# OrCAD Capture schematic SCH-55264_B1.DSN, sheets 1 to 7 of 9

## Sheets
1 09 Jumper Tables: size C; title: IMX-DSI-SDSB; rev: B1; company: NXP Semiconductors; note: SCH-55264 PDF: SPF-55264; note: 6501 William Cannon Drive West; note: Austin, TX 78735-8598
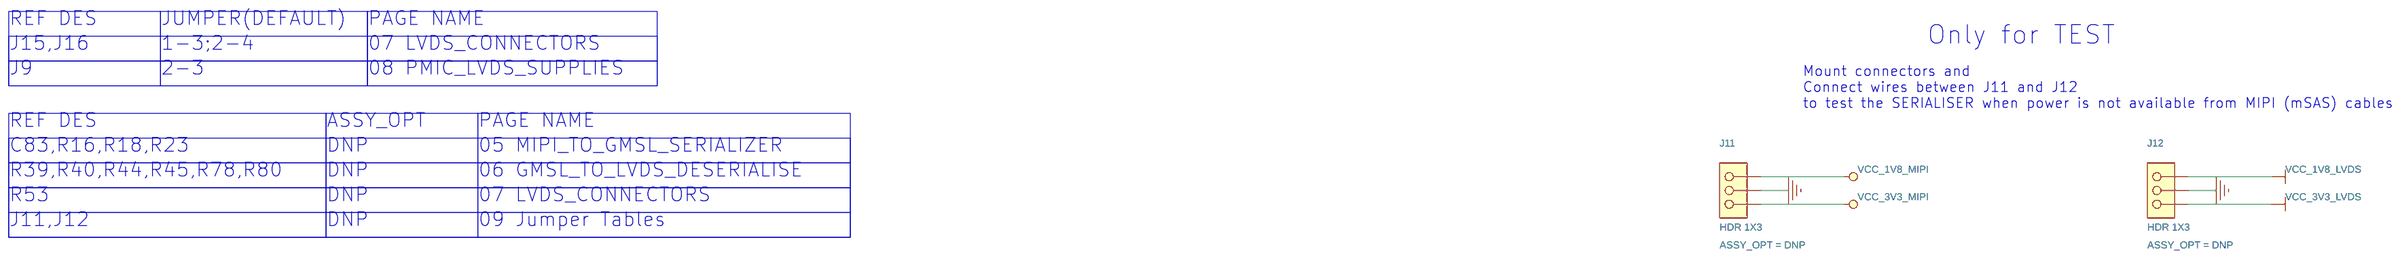
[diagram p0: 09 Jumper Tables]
2 01 TITLE
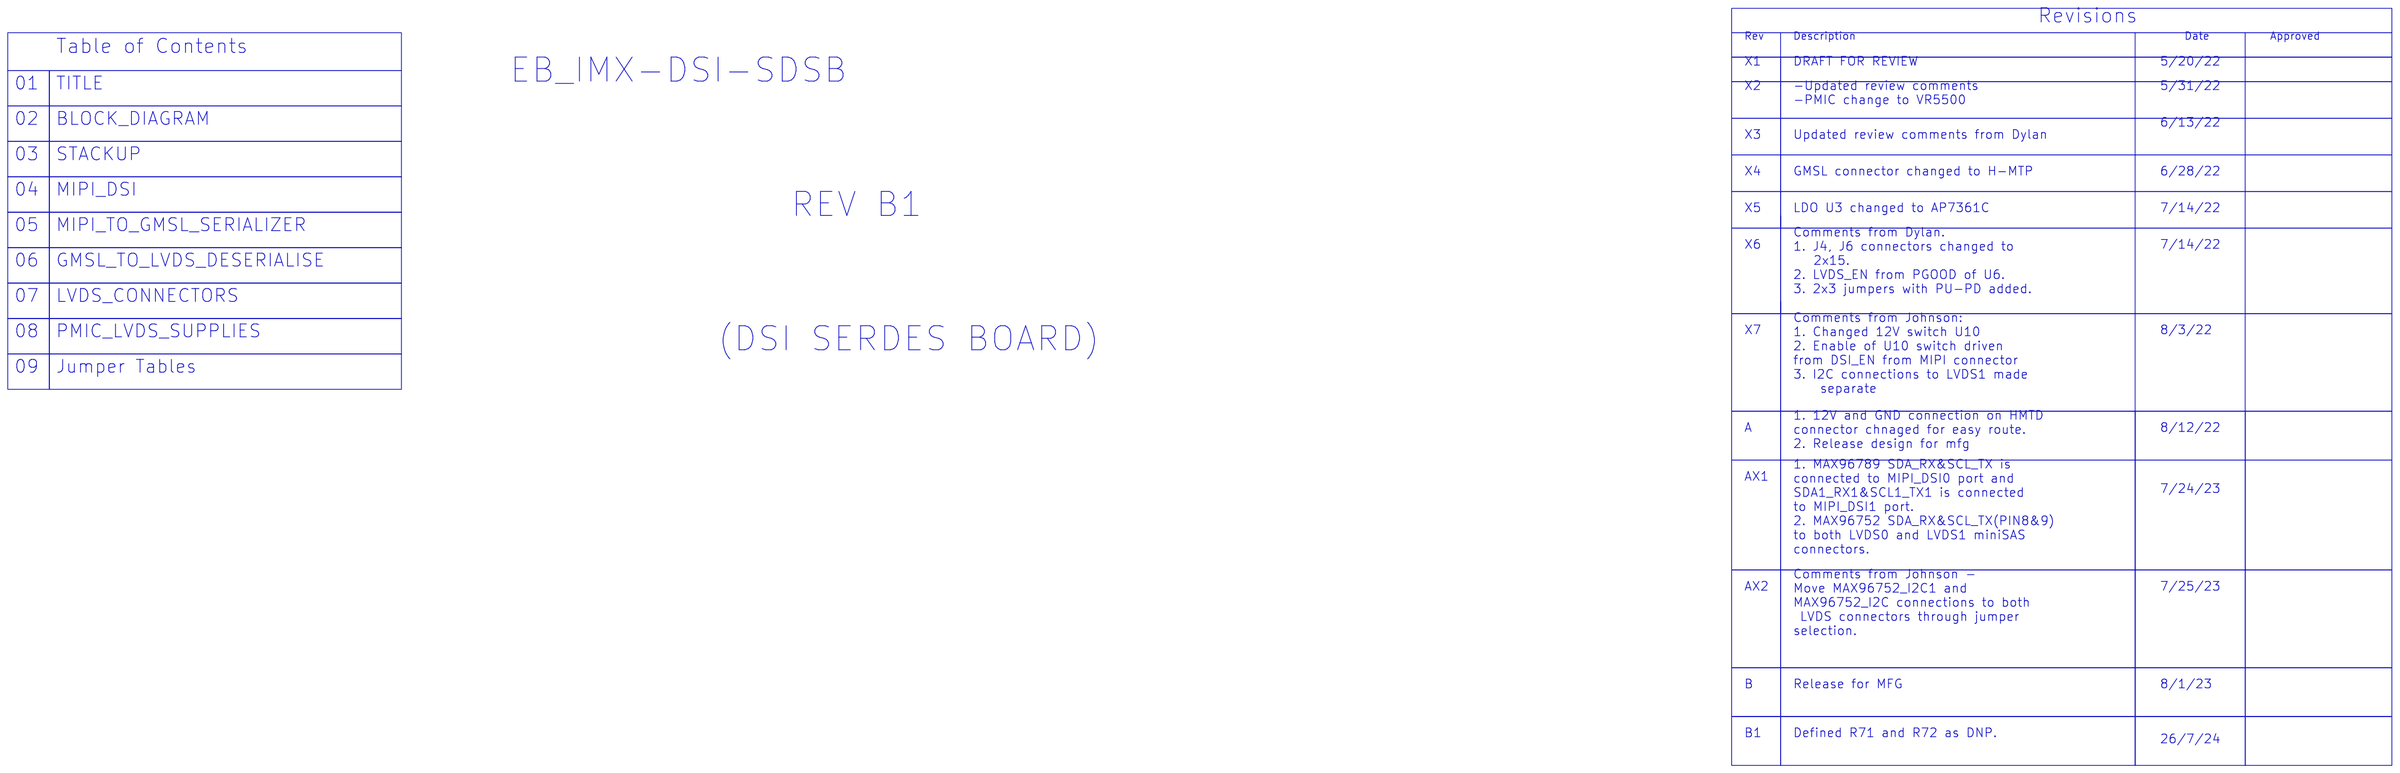
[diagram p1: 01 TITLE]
3 02 BLOCK_DIAGRAM
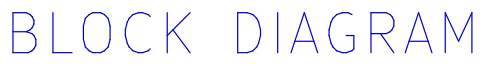
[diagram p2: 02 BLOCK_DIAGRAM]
4 03 STACKUP
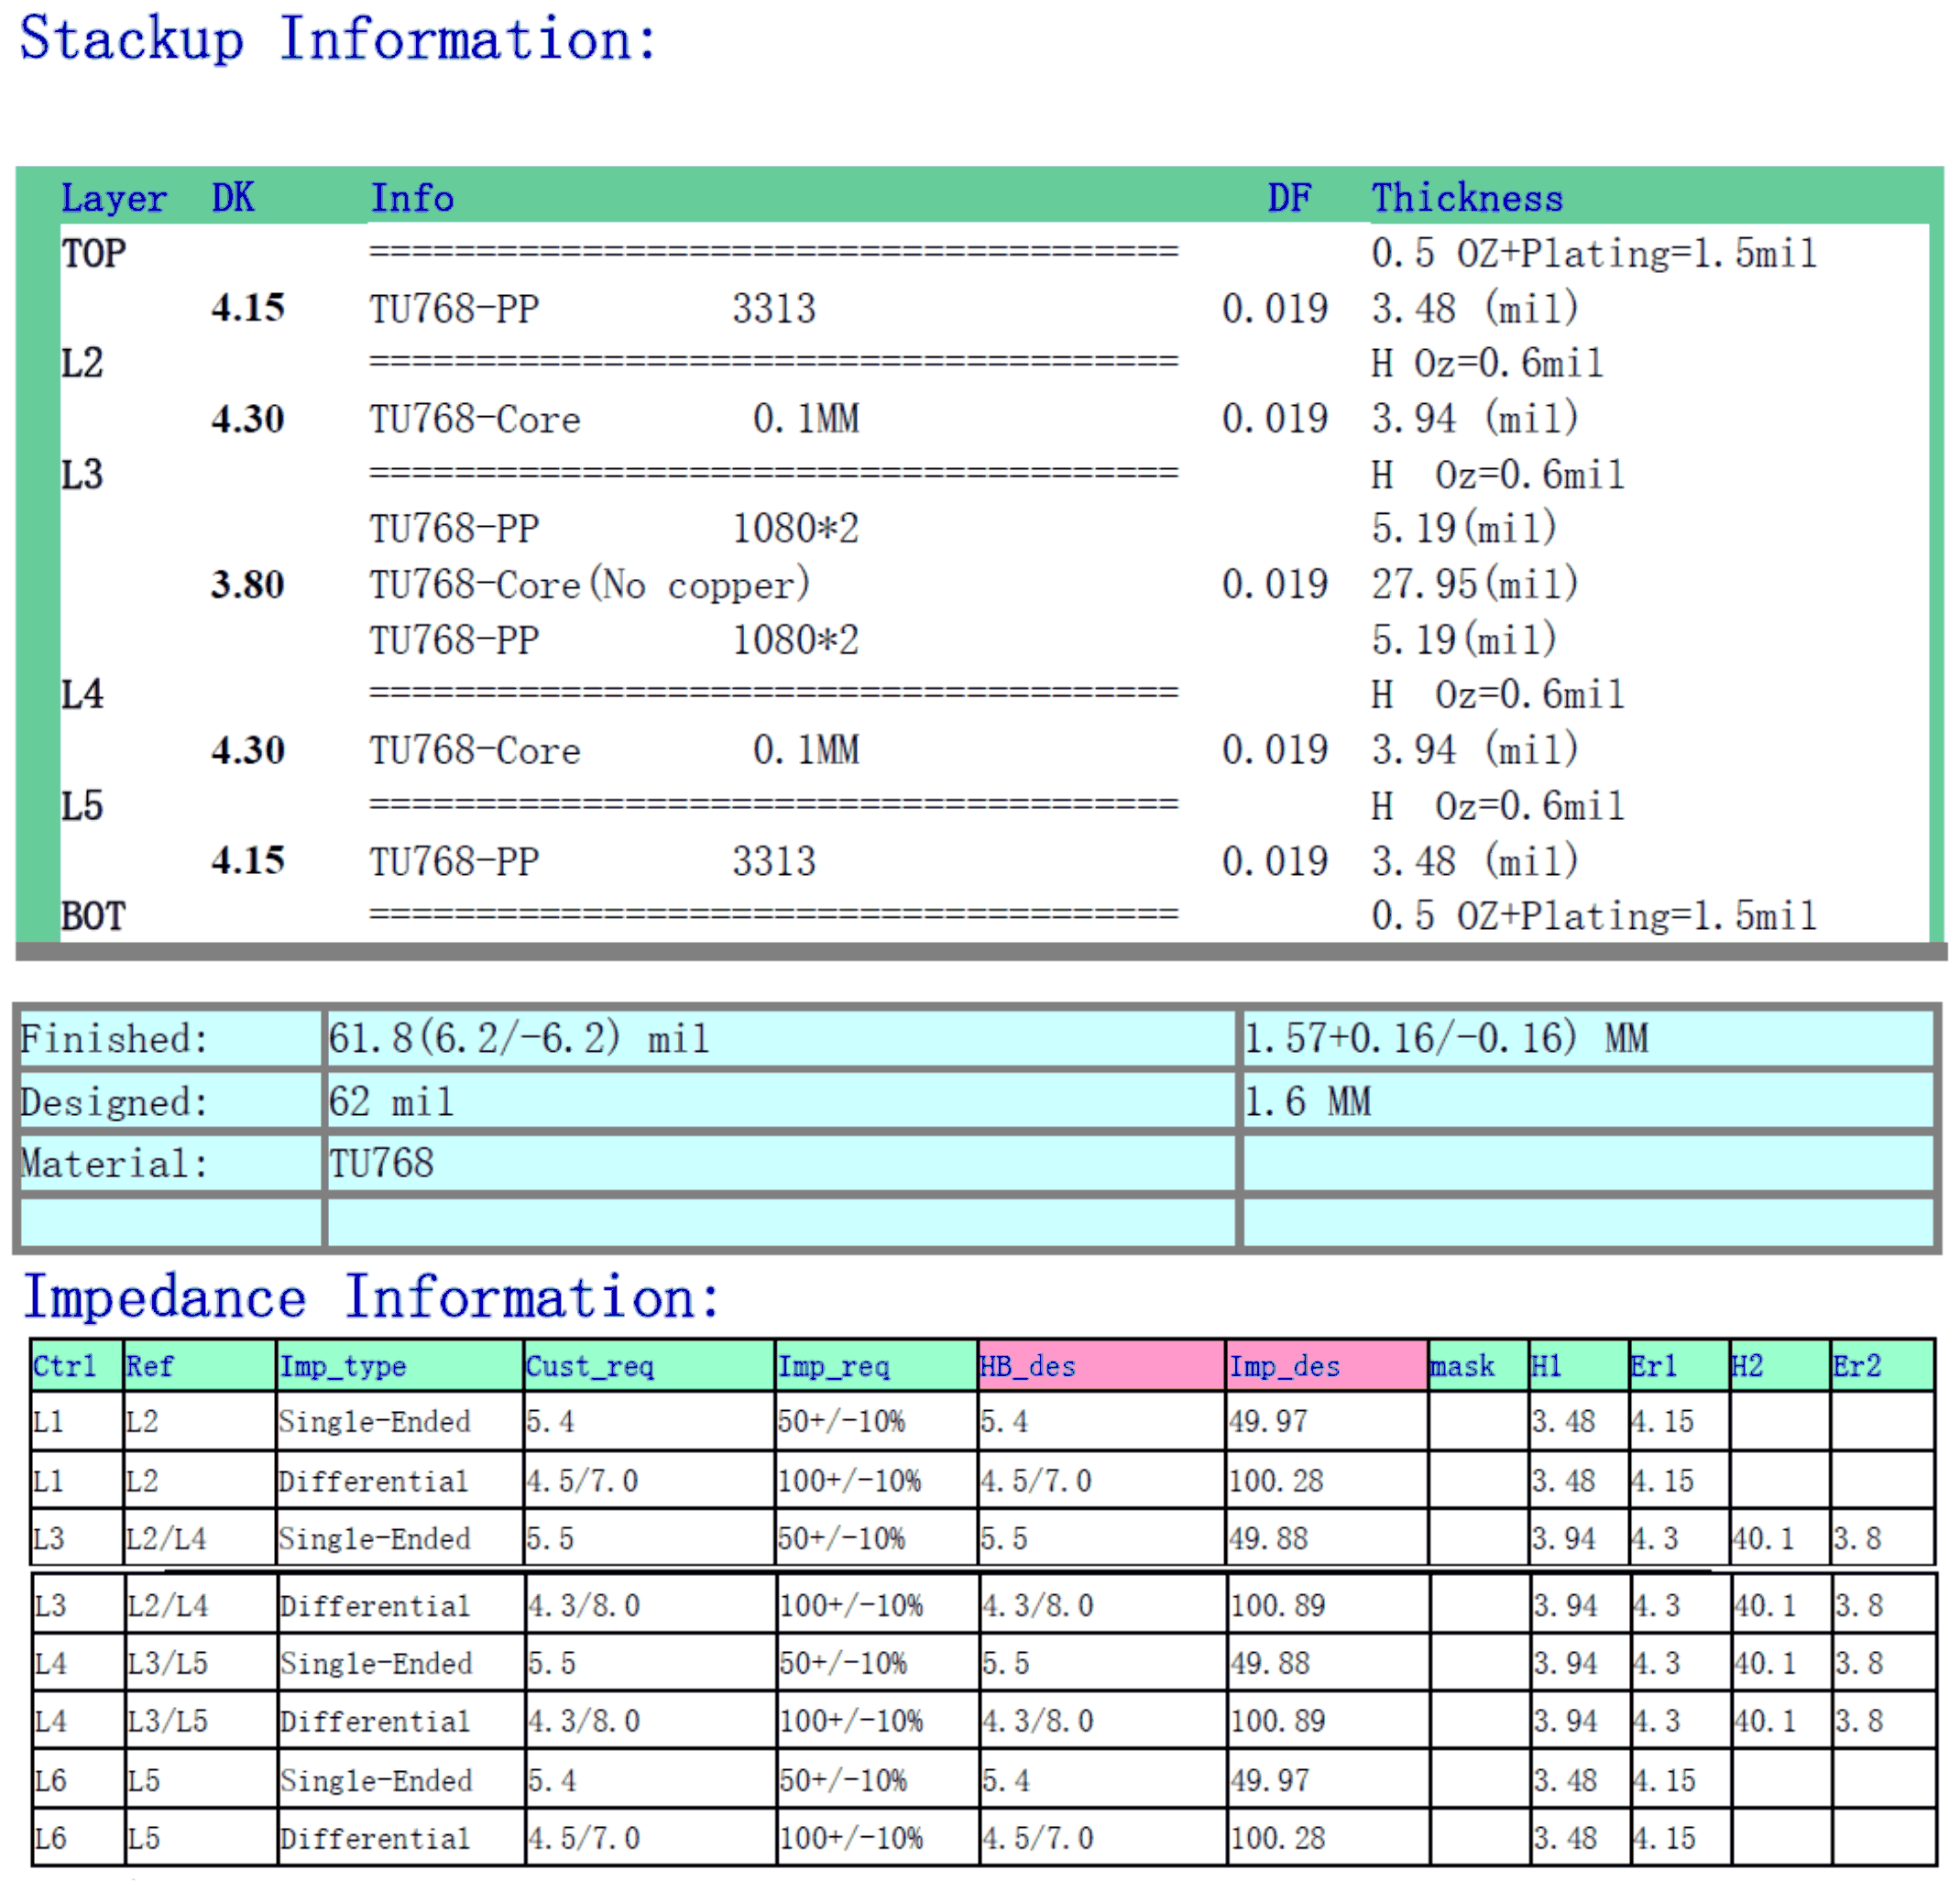
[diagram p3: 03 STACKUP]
5 04 MIPI_DSI: size C
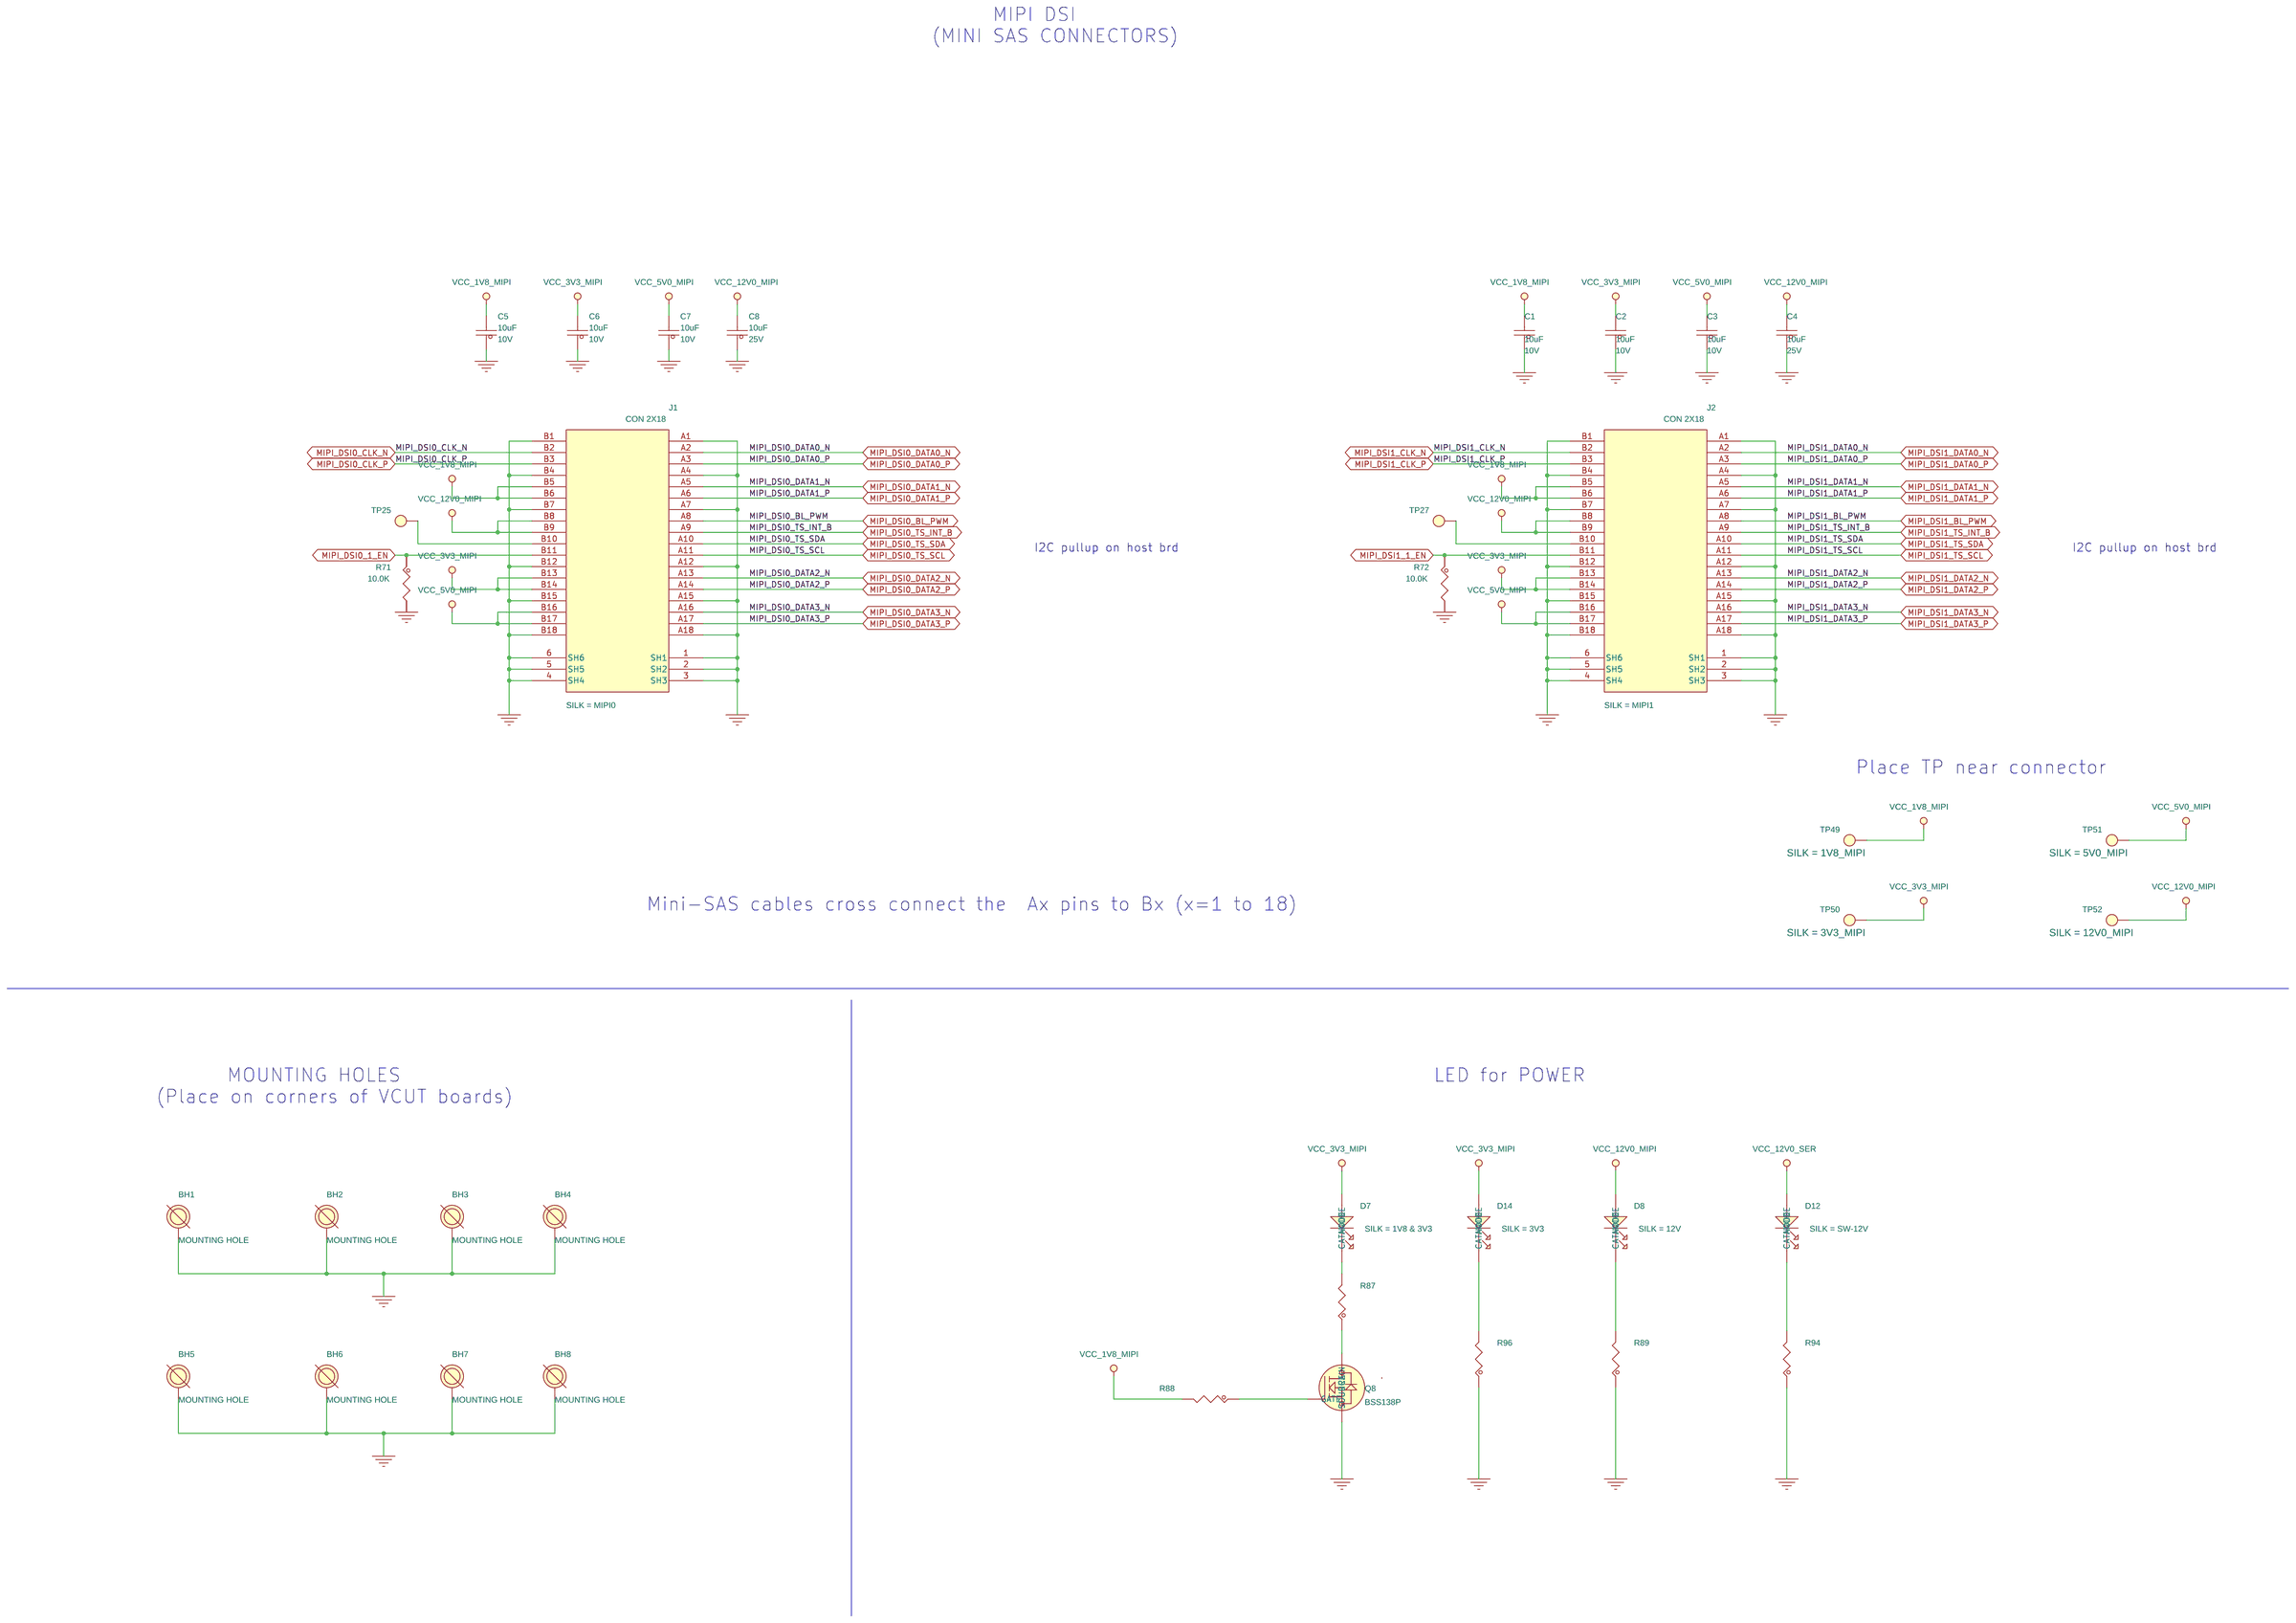
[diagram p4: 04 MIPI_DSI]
6 05 MIPI_TO_GMSL_SERIALIZER: size C
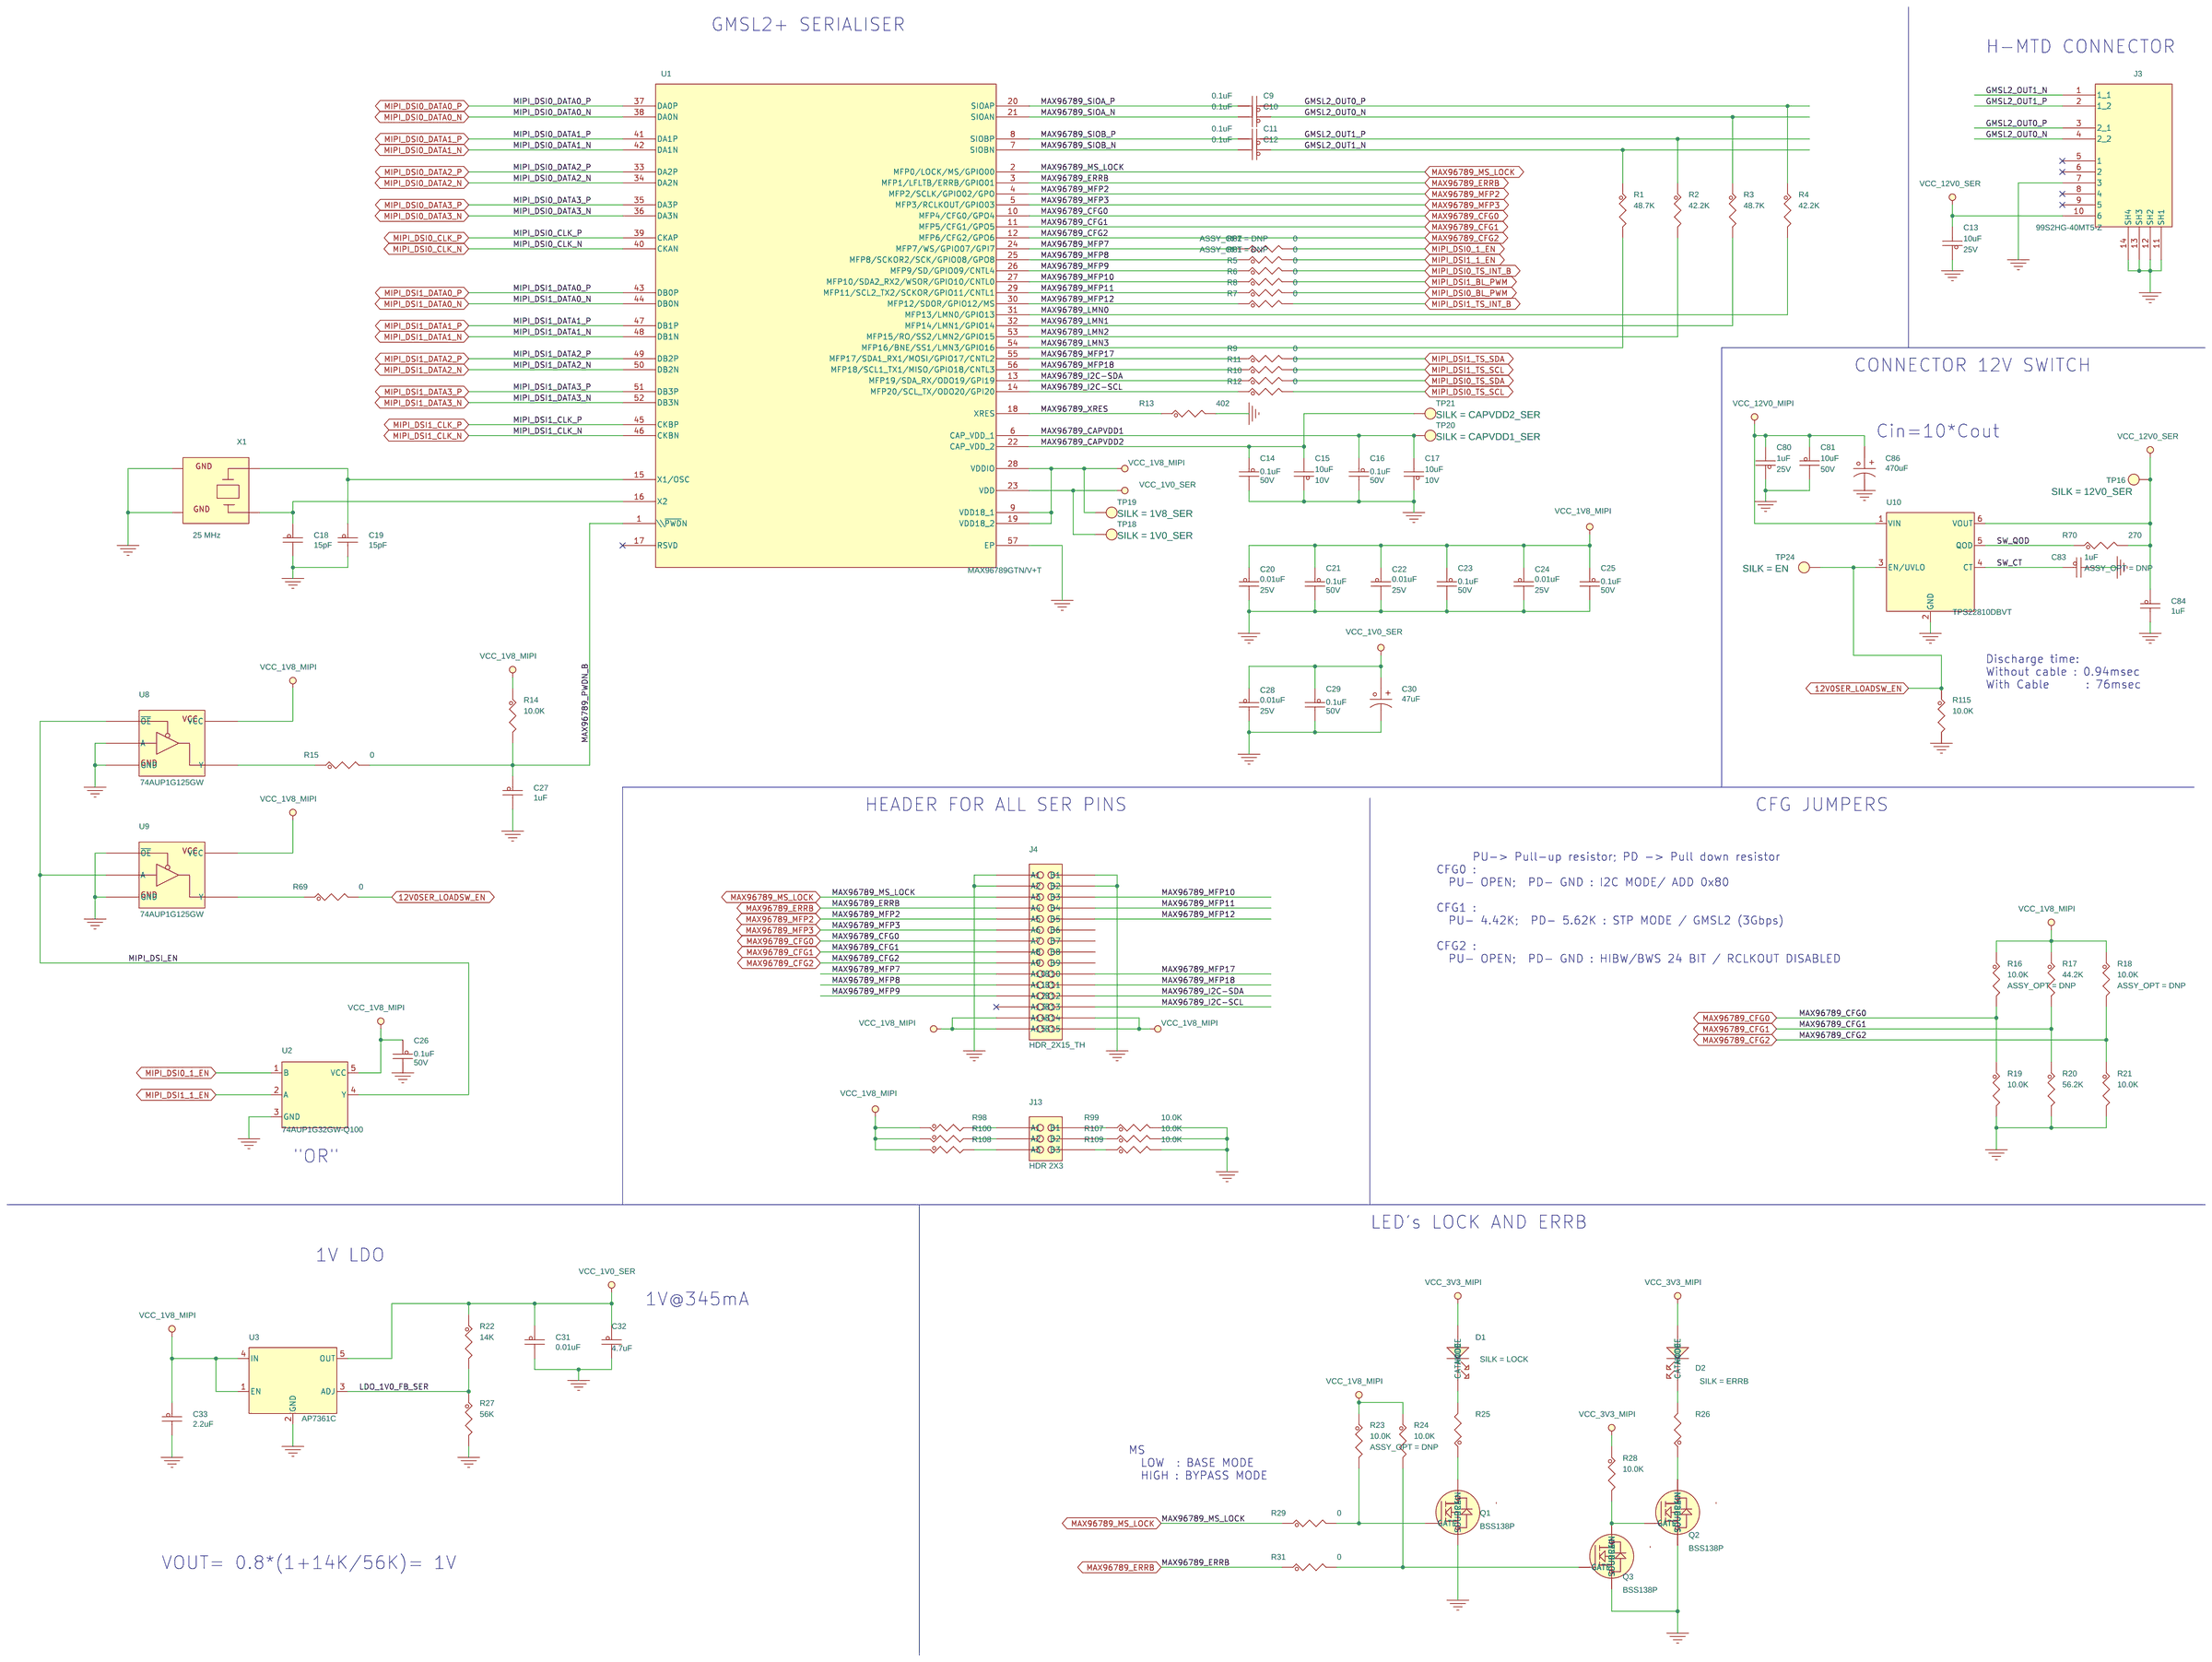
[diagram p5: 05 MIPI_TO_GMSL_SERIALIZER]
7 06 GMSL_TO_LVDS_DESERIALISE: size C
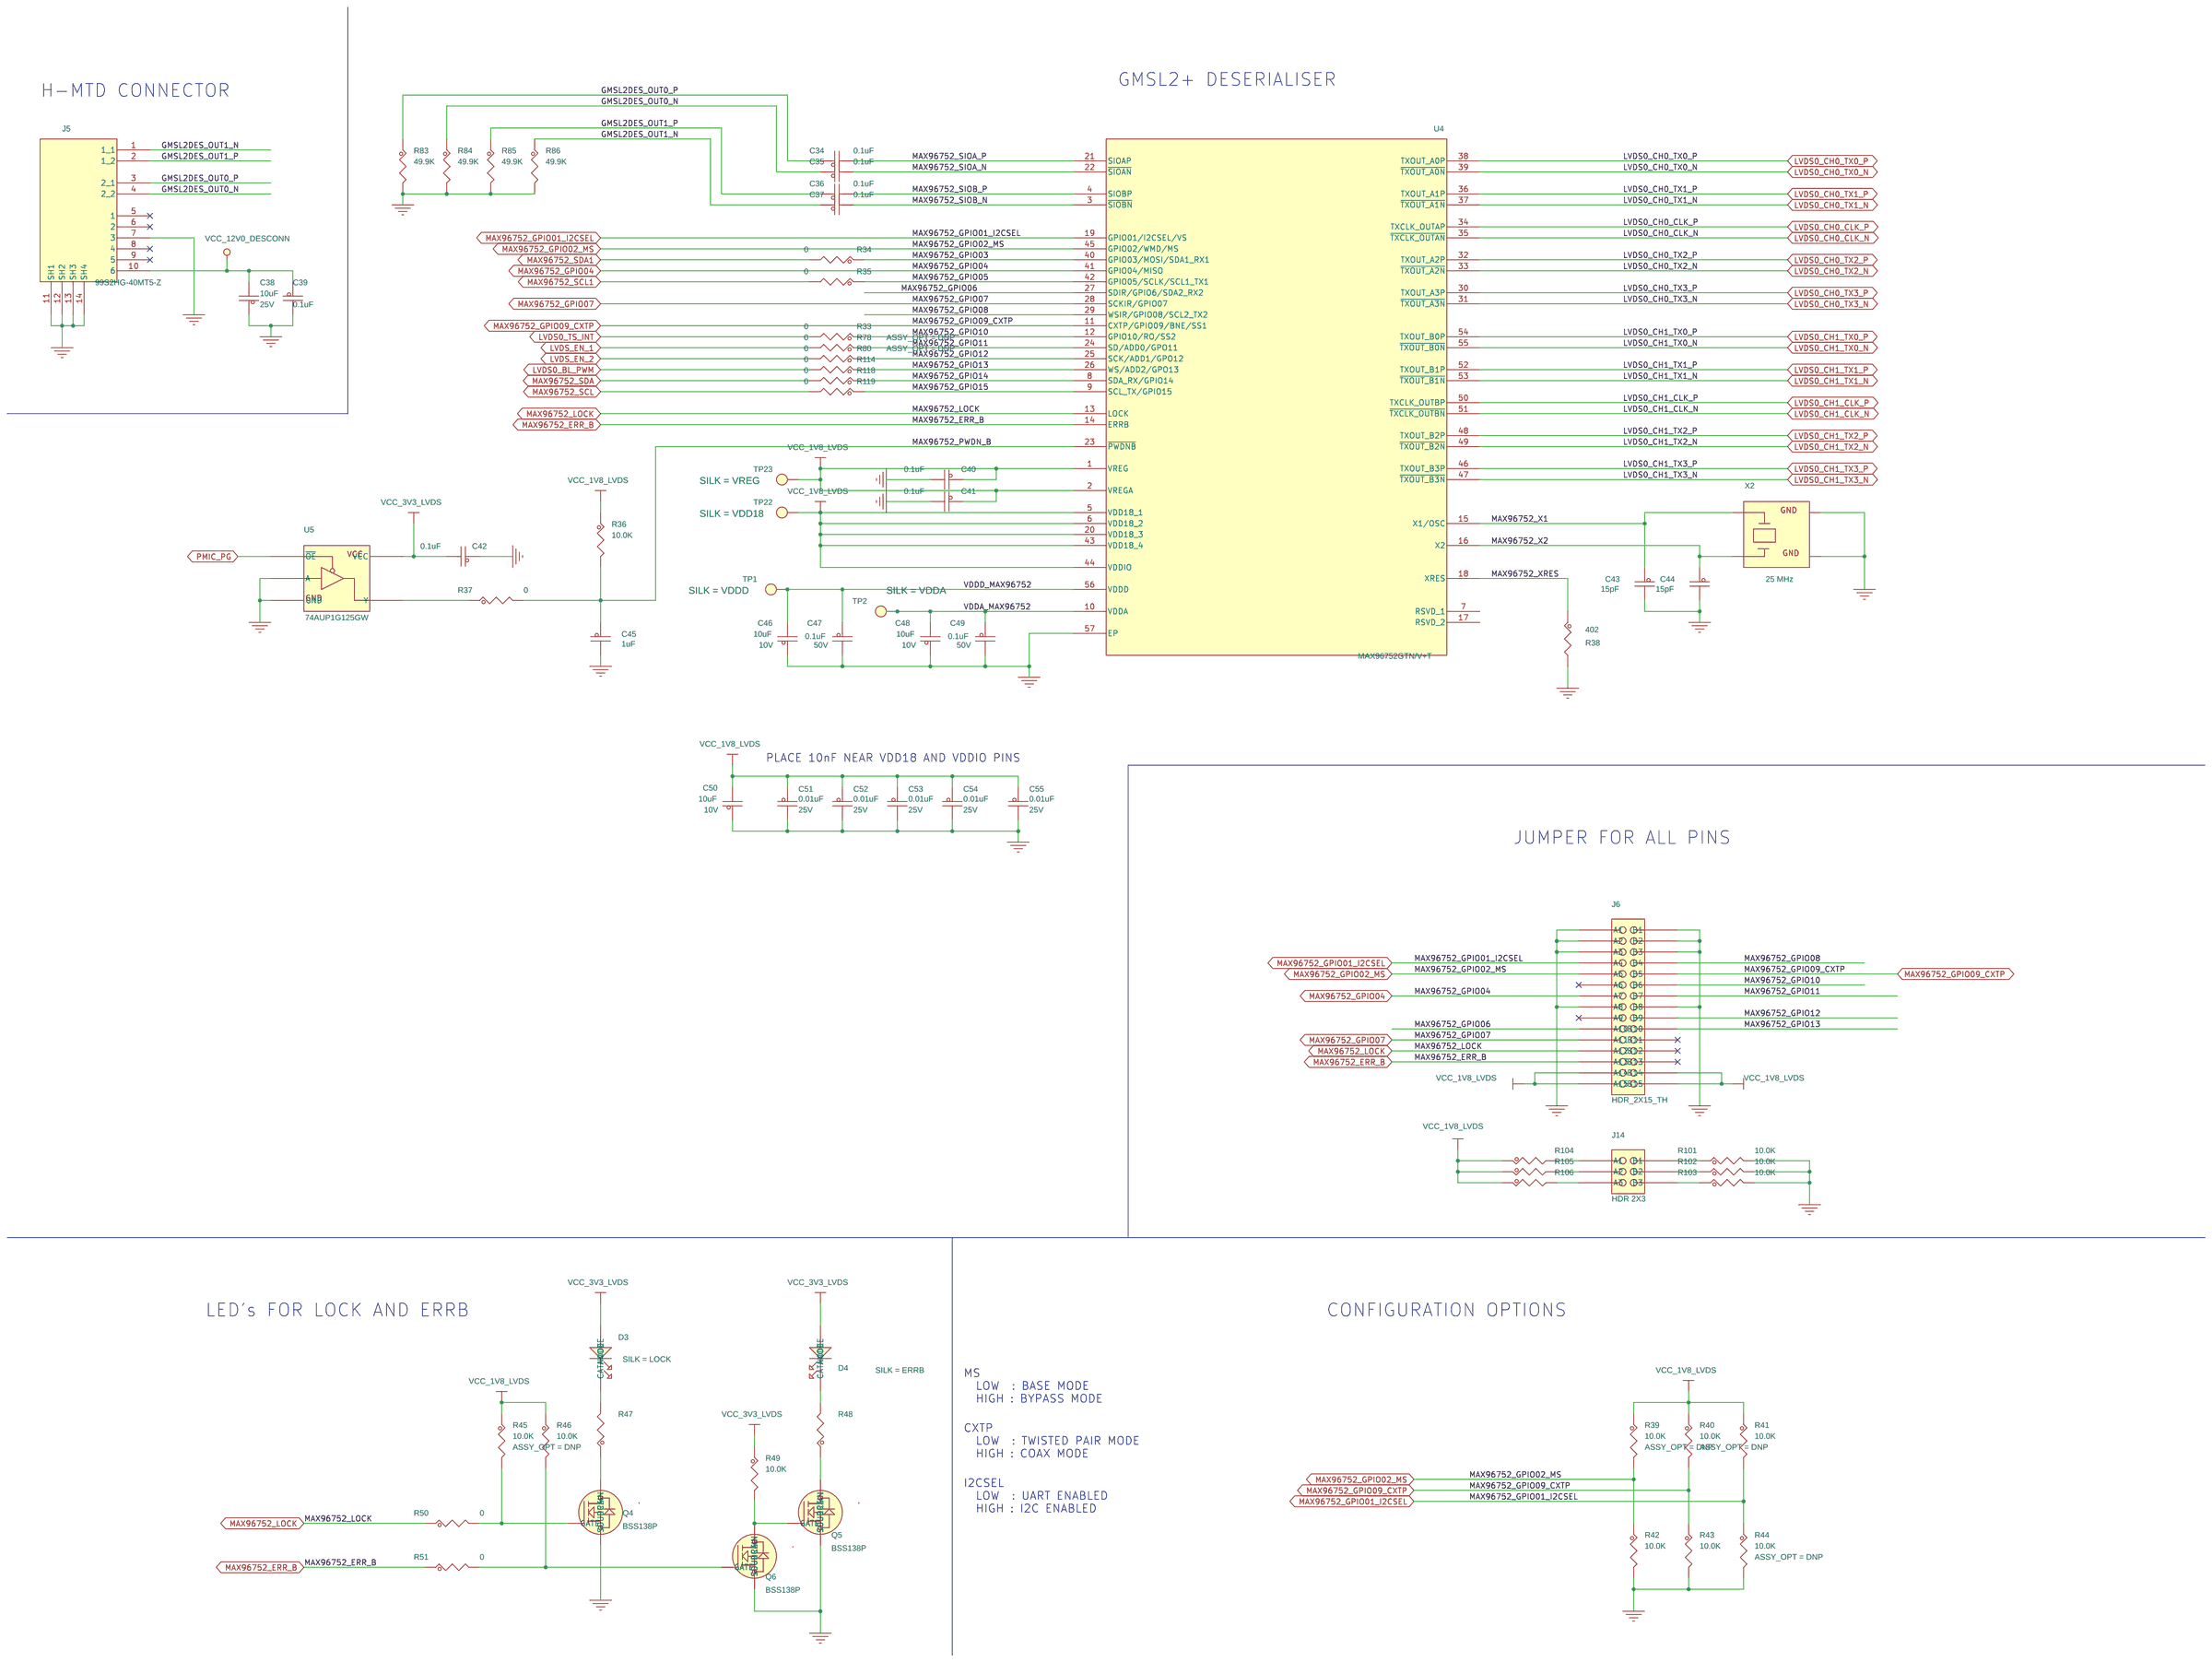
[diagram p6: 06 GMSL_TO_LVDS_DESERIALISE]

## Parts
sheet 04 MIPI_DSI
BH1  MOUNTING HOLE  [mh_c197-126t]
BH2  MOUNTING HOLE  [mh_c197-126t]
BH3  MOUNTING HOLE  [mh_c197-126t]
BH4  MOUNTING HOLE  [mh_c197-126t]
BH5  MOUNTING HOLE  [mh_c197-126t]
BH6  MOUNTING HOLE  [mh_c197-126t]
BH7  MOUNTING HOLE  [mh_c197-126t]
BH8  MOUNTING HOLE  [mh_c197-126t]
C1  10uF  [CC0603_OV]
C2  10uF  [CC0603_OV]
C3  10uF  [CC0603_OV]
C4  10uF  [CC0603_OV]
C5  10uF  [CC0603_OV]
C6  10uF  [CC0603_OV]
C7  10uF  [CC0603_OV]
C8  10uF  [CC0603_OV]
D7  LED GREEN  [LED_0603]
D8  LED GREEN  [LED_0603]
D12  LED GREEN  [LED_0603]
D14  LED GREEN  [LED_0603]
J1  CON 2X18  [con2x18_recep_wshell_0p8_sm_ra]
J2  CON 2X18  [con2x18_recep_wshell_0p8_sm_ra]
Q8  BSS138P  [sot23_a]
R71  10.0K  [RC0402_25]
R72  10.0K  [RC0402_25]
R87  1.00k  [RC0402_25]
R88  1.00k  [RC0402_25]
R89  5.23K  [RC0402_25]
R94  5.23K  [RC0402_25]
R96  1.00k  [RC0402_25]
TP25  TP_35MIL  [testpoint_35mil]
TP27  TP_35MIL  [testpoint_35mil]
TP49  TP_35MIL  [testpoint_35mil]
TP50  TP_35MIL  [testpoint_35mil]
TP51  TP_35MIL  [testpoint_35mil]
TP52  TP_35MIL  [testpoint_35mil]
sheet 05 MIPI_TO_GMSL_SERIALIZER
C9  0.1uF  [CC0402_25]
C10  0.1uF  [CC0402_25]
C11  0.1uF  [CC0402_25]
C12  0.1uF  [CC0402_25]
C13  10uF  [CC0603_OV]
C14  0.1uF  [CC0402_25]
C15  10uF  [CC0603_OV]
C16  0.1uF  [CC0402_25]
C17  10uF  [CC0603_OV]
C18  15pF  [CC0402_25]
C19  15pF  [CC0402_25]
C20  0.01uF  [CC0402_25]
C21  0.1uF  [CC0402_25]
C22  0.01uF  [CC0402_25]
C23  0.1uF  [CC0402_25]
C24  0.01uF  [CC0402_25]
C25  0.1uF  [CC0402_25]
C26  0.1uF  [CC0402_25]
C27  1uF  [cc0402_tol0p2]
C28  0.01uF  [CC0402_25]
C29  0.1uF  [CC0402_25]
C30  47uF  [case_d]
C31  0.01uF  [CC0402_25]
C32  4.7uF  [CC0805_OV]
C33  2.2uF  [CC0402_25]
C80  1uF  [cc0402_tol0p2]
C81  10uF  [CC1210]
C83  1uF  [cc0402_tol0p2]
C84  1uF  [cc0402_tol0p2]
C86  470uF  [cap_10p5_rad]
D1  LED GREEN  [LED_0603]
D2  RED LED  [LED_0603]
J3  99S2HG-40MT5-Z  [con_99s2hg_40mt5_ra_th]
J4  HDR_2X15_TH  [hdr215_a_338h]
J13  HDR 2X3  [HDR203]
Q1  BSS138P  [sot23_a]
Q2  BSS138P  [sot23_a]
Q3  BSS138P  [sot23_a]
R1  48.7K  [RC0402_25]
R2  42.2K  [RC0402_25]
R3  48.7K  [RC0402_25]
R4  42.2K  [RC0402_25]
R5  0  [RC0402_25]
R6  0  [RC0402_25]
R7  0  [RC0402_25]
R8  0  [RC0402_25]
R9  0  [RC0402_25]
R10  0  [RC0402_25]
R11  0  [RC0402_25]
R12  0  [RC0402_25]
R13  402  [RC0402_25]
R14  10.0K  [RC0402_25]
R15  0  [RC0402_25]
R16  10.0K  [RC0402_25]
R17  44.2K  [RC0402_25]
R18  10.0K  [RC0402_25]
R19  10.0K  [RC0402_25]
R20  56.2K  [RC0402_25]
R21  10.0K  [RC0402_25]
R22  14K  [RC0402_25]
R23  10.0K  [RC0402_25]
R24  10.0K  [RC0402_25]
R25  1.00k  [RC0402_25]
R26  1.00k  [RC0402_25]
R27  56K  [RC0402_25]
R28  10.0K  [RC0402_25]
R29  0  [RC0402_25]
R31  0  [RC0402_25]
R69  0  [RC0402_25]
R70  270  [RC0805_OV]
R81  0  [RC0402_25]
R82  0  [RC0402_25]
R98  1.00k  [RC0402_25]
R99  10.0K  [RC0402_25]
R100  1.00k  [RC0402_25]
R107  10.0K  [RC0402_25]
R108  1.00k  [RC0402_25]
R109  10.0K  [RC0402_25]
R115  10.0K  [RC0402_25]
TP16  TP_35MIL  [testpoint_35mil]
TP18  TP_35MIL  [testpoint_35mil]
TP19  TP_35MIL  [testpoint_35mil]
TP20  TP_35MIL  [testpoint_35mil]
TP21  TP_35MIL  [testpoint_35mil]
TP24  TP_35MIL  [testpoint_35mil]
U1  MAX96789GTN/V+T  [qfn56_0p5_8x8_ep4p6]
U2  74AUP1G32GW-Q100  [SC70-5]
U3  AP7361C  [sot-89-5]
U8  74AUP1G125GW  [SC70-5]
U9  74AUP1G125GW  [SC70-5]
U10  TPS22810DBVT  [SOT23-6]
X1  25 MHz  [osc4_3p2x2p5_sm]
sheet 06 GMSL_TO_LVDS_DESERIALISE
C34  0.1uF  [CC0402_25]
C35  0.1uF  [CC0402_25]
C36  0.1uF  [CC0402_25]
C37  0.1uF  [CC0402_25]
C38  10uF  [CC0603_OV]
C39  0.1uF  [CC0402_25]
C40  0.1uF  [CC0402_25]
C41  0.1uF  [CC0402_25]
C42  0.1uF  [CC0402_25]
C43  15pF  [CC0402_25]
C44  15pF  [CC0402_25]
C45  1uF  [cc0402_tol0p2]
C46  10uF  [CC0603_OV]
C47  0.1uF  [CC0402_25]
C48  10uF  [CC0603_OV]
C49  0.1uF  [CC0402_25]
C50  10uF  [CC0603_OV]
C51  0.01uF  [CC0402_25]
C52  0.01uF  [CC0402_25]
C53  0.01uF  [CC0402_25]
C54  0.01uF  [CC0402_25]
C55  0.01uF  [CC0402_25]
D3  LED GREEN  [LED_0603]
D4  RED LED  [LED_0603]
J5  99S2HG-40MT5-Z  [con_99s2hg_40mt5_ra_th]
J6  HDR_2X15_TH  [hdr215_a_338h]
J14  HDR 2X3  [HDR203]
Q4  BSS138P  [sot23_a]
Q5  BSS138P  [sot23_a]
Q6  BSS138P  [sot23_a]
R33  0  [RC0402_25]
R34  0  [RC0402_25]
R35  0  [RC0402_25]
R36  10.0K  [RC0402_25]
R37  0  [RC0402_25]
R38  402  [RC0402_25]
R39  10.0K  [RC0402_25]
R40  10.0K  [RC0402_25]
R41  10.0K  [RC0402_25]
R42  10.0K  [RC0402_25]
R43  10.0K  [RC0402_25]
R44  10.0K  [RC0402_25]
R45  10.0K  [RC0402_25]
R46  10.0K  [RC0402_25]
R47  1.00k  [RC0402_25]
R48  1.00k  [RC0402_25]
R49  10.0K  [RC0402_25]
R50  0  [RC0402_25]
R51  0  [RC0402_25]
R78  0  [RC0402_25]
R80  0  [RC0402_25]
R83  49.9K  [RC0402_25]
R84  49.9K  [RC0402_25]
R85  49.9K  [RC0402_25]
R86  49.9K  [RC0402_25]
R101  10.0K  [RC0402_25]
R102  10.0K  [RC0402_25]
R103  10.0K  [RC0402_25]
R104  1.00k  [RC0402_25]
R105  1.00k  [RC0402_25]
R106  1.00k  [RC0402_25]
R114  0  [RC0402_25]
R118  0  [RC0402_25]
R119  0  [RC0402_25]
TP1  TP_35MIL  [testpoint_35mil]
TP2  TP_35MIL  [testpoint_35mil]
TP22  TP_35MIL  [testpoint_35mil]
TP23  TP_35MIL  [testpoint_35mil]
U4  MAX96752GTN/V+T  [qfn56_0p5_8x8_ep4p6]
U5  74AUP1G125GW  [SC70-5]
X2  25 MHz  [osc4_3p2x2p5_sm]
sheet 09 Jumper Tables
J11  HDR 1X3  [hdr103_a_344h]
J12  HDR 1X3  [hdr103_a_344h]

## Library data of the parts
BH1-BH8 = MOUNT_HOLE: MOUNTING HOLE DRILL 126 PAD 197 PLATED TH NO PART TO ORDER; AGILE_PN: 280-77075; CAD_APPROVED: Yes; HEIGHT: 0.127; MFG_NAME01: N/A; MFG_PN01: N/A; ROHS: Yes
C1-C3 C5-C7 C15 C17 C46 C48 C50 = CAP_NP: CAP CER 10uF 25V 20% X5R 0603; AGILE_PN: 150-79272; CAD_APPROVED: Yes; EN: 102-1-01640; FPLIST: CC0603_OV,CC0603,0603_CC; HEIGHT: 1; MFG_NAME01: MURATA; MFG_PN01: GRM188R61E106MA73D; Package Size: 0603; ROHS: Yes; Rated Voltage: 25V; Temp Range: -55C to +85C; Tolerance: 20%; VOLTAGE: 10V
C4 C8 C13 C38 = CAP_NP: CAP CER 10uF 25V 20% X5R 0603; AGILE_PN: 150-79272; CAD_APPROVED: Yes; EN: 102-1-01982; FPLIST: CC0603_OV,CC0603,0603_CC; HEIGHT: 1; MFG_NAME01: MURATA; MFG_PN01: GRM188R61E106MA73D; Package Size: 0603; ROHS: Yes; Rated Voltage: 25V; TOL: 20%; Temp Range: -55C to +85C; Tolerance: 20%; VOLTAGE: 25V
D7 = LED: LED GRN SGL 20MA SMT; AGILE_PN: 370-75722; CAD_APPROVED: Yes; HEIGHT: 0.8; MFG_NAME01: AVAGO TECHNOLOGIES; MFG_PN01: HSMG-C190; ROHS: Yes; Rated Voltage: 2.6V; SILK: 1V8 & 3V3; Temp Range: -30°C to +85°C; VOLTAGE: 2.6V
D8 = LED: LED GRN SGL 20MA SMT; AGILE_PN: 370-75722; CAD_APPROVED: Yes; HEIGHT: 0.8; MFG_NAME01: AVAGO TECHNOLOGIES; MFG_PN01: HSMG-C190; ROHS: Yes; Rated Voltage: 2.6V; SILK: 12V; Temp Range: -30°C to +85°C; VOLTAGE: 2.6V
D12 = LED: LED GRN SGL 20MA SMT; AGILE_PN: 370-75722; CAD_APPROVED: Yes; HEIGHT: 0.8; MFG_NAME01: AVAGO TECHNOLOGIES; MFG_PN01: HSMG-C190; ROHS: Yes; Rated Voltage: 2.6V; SILK: SW-12V; Temp Range: -30°C to +85°C; VOLTAGE: 2.6V
D14 = LED: LED GRN SGL 20MA SMT; AGILE_PN: 370-75722; CAD_APPROVED: Yes; HEIGHT: 0.8; MFG_NAME01: AVAGO TECHNOLOGIES; MFG_PN01: HSMG-C190; ROHS: Yes; Rated Voltage: 2.6V; SILK: 3V3; Temp Range: -30°C to +85°C; VOLTAGE: 2.6V
J1 = CON_2X18_SH6: CON 2X18 RA SKT W/SHELL SMT 0.8MM SP 339H AU; 3D_Mechanical_Footprint_File: http://fcl.am.freescale.net/ALLEGRO/step/con2x18_recep_wshell_0p8_sm_ra.STEP; AGILE_PN: 211-80139; CAD_APPROVED: Yes; EN: 201-1-00825; HEIGHT: 8.6; MFG_NAME01: MOLEX; MFG_PN01: 075783-0132; ROHS: NULL; SILK: MIPI0; Temp Range: -40 °C to +80 °C
J2 = CON_2X18_SH6: CON 2X18 RA SKT W/SHELL SMT 0.8MM SP 339H AU; 3D_Mechanical_Footprint_File: http://fcl.am.freescale.net/ALLEGRO/step/con2x18_recep_wshell_0p8_sm_ra.STEP; AGILE_PN: 211-80139; CAD_APPROVED: Yes; EN: 201-1-00825; HEIGHT: 8.6; MFG_NAME01: MOLEX; MFG_PN01: 075783-0132; ROHS: NULL; SILK: MIPI1; Temp Range: -40 °C to +80 °C
Q1-Q6 Q8 = MOSFET_N: TRAN NMOS 60V 360MA AEC-Q101 TO-236AB; AGILE_PN: 480-79842; CAD_APPROVED: Yes; HEIGHT: 1.1; MFG_NAME01: NEXPERIA; MFG_PN01: BSS138P,215; ROHS: Yes; Temp Range: -65°C ~ 150°C
R14 R19 R21 R24 R28 R36 R41-R43 R46 R49 R71 R72 R99 R101-R103 R107 R109 R115 = RES: RES MF 10.0K 1/16W 1% AEC-Q200 0402; AGILE_PN: 470-75416; CAD_APPROVED: Yes; HEIGHT: 0.4; MFG_NAME01: KOA SPEER; MFG_PN01: RK73H1ETTP1002F; ROHS: Yes; Temp Range: –55 °C to +155 °C; Tolerance: 1%
R25 R26 R47 R48 R87 R88 R96 R98 R100 R104-R106 R108 = RES: RES MF 1.00k Ohm 1/16W 1% AEC-Q200 0402; 3D_Mechanical_Footprint_File: http://fcl.am.freescale.net/ALLEGRO/step/rc0402_25.STEP; AGILE_PN: 470-80511; CAD_APPROVED: Yes; FPLIST: RC0402_25,RC0402_HD,0402_CC; HEIGHT: 0.4; MFG_NAME01: KOA SPEER; MFG_PN01: RK73H1ETTP1001F; ROHS: Yes; Tolerance: 1%; VOLTAGE: 50V
R89 R94 = RES: RES MF 5.23K  1/10W 1% AEC-Q200 0402; AGILE_PN: 470-81644; CAD_APPROVED: Yes; FPLIST: RC0402_25,RC0402_HD,0402_CC; HEIGHT: 0.40; MFG_NAME01: KOA SPEER; MFG_PN01: RK73H1ETTP5231F; ROHS: Yes; Temp Range: -55C to +155C; Tolerance: 1%; VOLTAGE: 50V
TP25 TP27 = T_POINT_R: TEST POINT PAD .035 SMT, no part to order; AGILE_PN: 510-75618; CAD_APPROVED: Yes; HEIGHT: 0.1; ROHS: Yes
TP49 = T_POINT_R: TEST POINT PAD .035 SMT, no part to order; AGILE_PN: 510-75618; CAD_APPROVED: Yes; HEIGHT: 0.1; ROHS: Yes; SILK: 1V8_MIPI
TP50 = T_POINT_R: TEST POINT PAD .035 SMT, no part to order; AGILE_PN: 510-75618; CAD_APPROVED: Yes; HEIGHT: 0.1; ROHS: Yes; SILK: 3V3_MIPI
TP51 = T_POINT_R: TEST POINT PAD .035 SMT, no part to order; AGILE_PN: 510-75618; CAD_APPROVED: Yes; HEIGHT: 0.1; ROHS: Yes; SILK: 5V0_MIPI
TP52 = T_POINT_R: TEST POINT PAD .035 SMT, no part to order; AGILE_PN: 510-75618; CAD_APPROVED: Yes; HEIGHT: 0.1; ROHS: Yes; SILK: 12V0_MIPI
C9-C12 C14 C16 C21 C23 C25 C26 C29 C34-C37 C40-C42 C47 C49 = CAP_NP: CAP CER 0.1uF 50V 10% X7R AEC-Q200 0402; AGILE_PN: 150-79461; CAD_APPROVED: Yes; HEIGHT: 0.55; MFG_NAME01: MURATA; MFG_PN01: GCM155R71H104KE02D; Package Size: 0402; ROHS: NULL; Rated Voltage: 50V; Temp Range: -55C to +125C; Tolerance: 10%; VOLTAGE: 50V
C18 C19 C43 C44 = CAP_NP: CAP CER 15pF 50V 5% C0G AEC-Q200 0402; AGILE_PN: 150-79220; CAD_APPROVED: Yes; HEIGHT: 0.55; MFG_NAME01: MURATA; MFG_PN01: GCM1555C1H150JA16; Package Size: 0402; ROHS: Yes; Rated Voltage: 50V; Temp Range: -55C to +125C; Tolerance: 5%; VOLTAGE: 50V
C20 C22 C24 C28 C31 C51-C55 = CAP_NP: CAP CER 0.01uF 25V 10% X7R AEC-Q200 0402; AGILE_PN: 150-79365; CAD_APPROVED: Yes; HEIGHT: 0.55; MFG_NAME01: MURATA; MFG_PN01: GCM155R71E103KA37D; Package Size: 0402; Package Type: f180mm Reel PAPER; ROHS: Yes; Rated Voltage: 25V; Temp Range: -55C to +125C; Tolerance: 10%; VOLTAGE: 25V
C27 C45 C84 = CAP_NP: CAP CER 1uF 25V 10% X6S AEC-Q200 0402; AGILE_PN: 150-80570; CAD_APPROVED: Yes; HEIGHT: 0.7; MFG_NAME01: MURATA; MFG_PN01: GRT155C81E105KE13D; Package Size: 1.1x0.6x0.6MM; Package Type: 0402; ROHS: Yes; Rated Voltage: 25V; Temp Range: -55C to +105C; Tolerance: 10%; VOLTAGE: 25V
C30 = CAP_POL: CAP TANT 47UF 25V 10% SIZE D; 3D_Mechanical_Footprint_File: http://fcl.am.freescale.net/ALLEGRO/step/CASE_D.step; AGILE_PN: 150-75813; CAD_APPROVED: Yes; HEIGHT: 3.2; MFG_NAME01: AVX; MFG_PN01: TPSD476K025R0125; Package Size: 7343; Package Type: 7" T/R; ROHS: Yes; Rated Voltage: 25V; Tolerance: 10%; VOLTAGE: 25V
C32 = CAP_NP: CAP CER 4.7uF 35V 10% X7S AEC-Q200 0805; AGILE_PN: 150-79910; CAD_APPROVED: Yes; FPLIST: CC0805_OV,CC0805,0805_CC; HEIGHT: 1.45; MFG_NAME01: MURATA; MFG_PN01: GCM21BC7YA475KE36; Package Size: 0805; ROHS: Yes; Rated Voltage: 35V; Temp Range: -55C to +125C; Tolerance: 10%; VOLTAGE: 35V
C33 = CAP_NP: CAP CER 2.2uF 16V 20% X5R 0402; AGILE_PN: 150-79929; CAD_APPROVED: Yes; HEIGHT: 0.6mm; MFG_NAME01: TAIYO YUDEN; MFG_PN01: MSASE105AB5225MFNA01; Package Size: 0402; ROHS: NULL; Rated Voltage: 16V; Temp Range: -55C to +85C; Tolerance: 20%; VOLTAGE: 16V
C80 = CAP_NP: CAP CER 1uF 25V 10% X6S AEC-Q200 0402; AGILE_PN: 150-80570; CAD_APPROVED: Yes; EN: 102-1-01982; FPLIST: CC0603_OV,CC0603,0603_CC; HEIGHT: 0.7; MFG_NAME01: MURATA; MFG_PN01: GRT155C81E105KE13D; Package Size: 1.1x0.6x0.6MM; Package Type: 0402; ROHS: Yes; Rated Voltage: 25V; TOL: 20%; Temp Range: -55C to +105C; Tolerance: 10%; VOLTAGE: 25V
C81 = CAP_NP: CAP CER 10uF 50V 10% X7S AEC-Q200 1210; AGILE_PN: 150-79213; CAD_APPROVED: Yes; FPLIST: CC1210,1210_CC; HEIGHT: 2.8; MFG_NAME01: MURATA; MFG_PN01: GCM32EC71H106KA03; Package Size: 1210; ROHS: Yes; Rated Voltage: 50V; Temp Range: -55C to +125C; Tolerance: 10%; VOLTAGE: 50V
C83 = CAP_NP: CAP CER 1uF 25V 10% X6S AEC-Q200 0402; AGILE_PN: 150-80570; ASSY_OPT: DNP; CAD_APPROVED: Yes; HEIGHT: 0.7; MFG_NAME01: MURATA; MFG_PN01: GRT155C81E105KE13D; Package Size: 1.1x0.6x0.6MM; Package Type: 0402; ROHS: Yes; Rated Voltage: 25V; Temp Range: -55C to +105C; Tolerance: 10%; VOLTAGE: 25V
C86 = CAP_POL: CAP ALEL 470uF 35V 20% TH RADIAL; AGILE_PN: 150-79840; CAD_APPROVED: Yes; HEIGHT: 17; MFG_NAME01: MULTICOMP; MFG_PN01: MCGPR35V477M10X21; Package Size: 10MM RADIAL; ROHS: Yes; Rated Voltage: 35V; Tolerance: 20%
D1 D3 = LED: LED GRN SGL 20MA SMT; AGILE_PN: 370-75722; CAD_APPROVED: Yes; HEIGHT: 0.8; MFG_NAME01: AVAGO TECHNOLOGIES; MFG_PN01: HSMG-C190; ROHS: Yes; Rated Voltage: 2.6V; SILK: LOCK; Temp Range: -30°C to +85°C; VOLTAGE: 2.6V
D2 D4 = LED: LED RED SGL 30MA SMT 0603; AGILE_PN: 370-75905; CAD_APPROVED: Yes; HEIGHT: 0.65; MFG_NAME01: VISHAY INTERTECHNOLOGY; MFG_PN01: TLMS1100-GS08; ROHS: Yes; Rated Voltage: 3V; SILK: ERRB; Temp Range: -40 °C to +100 °C; VOLTAGE: 3V
J3 J5 = CON14_RA_TH: CON 10 PLUG TH RA 2.54MM SP 553H AU 94L; 3D_Mechanical_Footprint_File: http://fcl.am.freescale.net/ALLEGRO/step/con_99s2hg_40mt5_ra_th.STEP; AGILE_PN: 210-83184; CAD_APPROVED: Yes; HEIGHT: 14.05; MFG_NAME01: Rosenberger; Package Type: TH; ROHS: Yes; Temp Range: -40 °C to +105 °C
J4 J6 = CONN_HDR_15X2: HDR 2X15 TH 100MIL CTR 338H AU 100L; 3D_Mechanical_Footprint_File: http://fcl.am.freescale.net/ALLEGRO/step/hdr215_a_338h.STEP; AGILE_PN: 210-80996; CAD_APPROVED: Yes; HEIGHT: 8.6; MFG_NAME01: SAMTEC; MFG_PN01: TSW-115-07-G-D; ROHS: Yes
J13 J14 = CONN_HDR_3X2: HDR 2X3 TH 100MIL CTR 338H AU 100L; 3D_Mechanical_Footprint_File: http://fcl.am.freescale.net/ALLEGRO/step/hdr203.STEP; AGILE_PN: 210-81396; CAD_APPROVED: Yes; HEIGHT: 8.59; MFG_NAME01: SAMTEC; MFG_PN01: TSW-103-07-G-D; Package Size: 7.62x5.08m; ROHS: Yes; Temp Range: -55C to +125C
R1 R3 = RES: RES MF 48.7K 1/10W 1% AEC-Q200 0402; AGILE_PN: 470-31025; CAD_APPROVED: Yes; HEIGHT: 0.40; MFG_NAME01: KOA SPEER; MFG_PN01: RK73H1ETTP4872F; ROHS: Yes; Temp Range: -55C to +155C; Tolerance: 1%
R2 R4 = RES: RES MF 42.2K 1/10W 1% AEC-Q200 0402; AGILE_PN: 470-81723; CAD_APPROVED: Yes; HEIGHT: 0.40; MFG_NAME01: KOA SPEER; MFG_PN01: RK73H1ETTP4222F; ROHS: Yes; Temp Range: -55C to +155C; Tolerance: 1%
R5-R12 R15 R29 R31 R33-R35 R37 R50 R51 R69 R114 R118 R119 = RES: RES MF ZERO OHM 1/16W -- AEC-Q200 0402; AGILE_PN: 470-80742; CAD_APPROVED: Yes; HEIGHT: 0.45; MFG_NAME01: VISHAY INTERTECHNOLOGY; MFG_PN01: CRCW04020000Z0ED; ROHS: NULL; Temp Range: -55° C to +155° C
R13 R38 = RES: RES MF 402 OHM 1/10W 1% AEC-Q200 0402; AGILE_PN: 470-81548; CAD_APPROVED: Yes; HEIGHT: 0.40; MFG_NAME01: KOA SPEER; MFG_PN01: RK73H1ETTP4020F; ROHS: Yes; Temp Range: -55C to +155C; Tolerance: 1%; VOLTAGE: 50V
R16 R18 R23 R39 R40 R44 R45 = RES: RES MF 10.0K 1/16W 1% AEC-Q200 0402; AGILE_PN: 470-75416; ASSY_OPT: DNP; CAD_APPROVED: Yes; HEIGHT: 0.4; MFG_NAME01: KOA SPEER; MFG_PN01: RK73H1ETTP1002F; ROHS: Yes; Temp Range: –55 °C to +155 °C; Tolerance: 1%
R17 = RES: RES MF 44.2K 1/16W 1% AEC-Q200 0402; AGILE_PN: 470-81745; CAD_APPROVED: Yes; HEIGHT: 0.40; MFG_NAME01: VISHAY INTERTECHNOLOGY; MFG_PN01: CRCW040244K2FKED; ROHS: Yes; Temp Range: -55C to +155C; Tolerance: 1%; VOLTAGE: 50V
R20 = RES: RES MF 56.2K 1/10W 1% AEC-Q200 0402; AGILE_PN: 470-82784; CAD_APPROVED: Yes; HEIGHT: 0.4; MFG_NAME01: PANASONIC; MFG_PN01: ERJ-2RKF5622X; Package Size: 0402 (1005 Metric); ROHS: Yes; Temp Range: -55C to +155C; Tolerance: 1%
R22 = RES: RES MF 14K 1/10W 1% AEC-Q200 0402; AGILE_PN: 470-81689; CAD_APPROVED: Yes; HEIGHT: 0.40; MFG_NAME01: KOA SPEER; MFG_PN01: RK73H1ETTP1402F; ROHS: Yes; Temp Range: -55C to +155C; Tolerance: 1%; VOLTAGE: 50V
R27 = RES: RES MF 56K 1/10W 1% AEC-Q200 0402; AGILE_PN: 470-31032; CAD_APPROVED: Yes; HEIGHT: 0.40; MFG_NAME01: KOA SPEER; MFG_PN01: RK73H1ETTP5602F; ROHS: Yes; Temp Range: -55C to +155C; Tolerance: 1%
R70 = RES: RES MF 270 OHM 1/2W 1% AEC-Q200 0805; AGILE_PN: 470-81209; CAD_APPROVED: Yes; HEIGHT: 0.6; MFG_NAME01: VISHAY INTERTECHNOLOGY; MFG_PN01: CRCW0805270RFKEAHP; ROHS: Yes; Tolerance: 1%
R78 R80-R82 = RES: RES MF ZERO OHM 1/16W -- AEC-Q200 0402; AGILE_PN: 470-80742; ASSY_OPT: DNP; CAD_APPROVED: Yes; HEIGHT: 0.45; MFG_NAME01: VISHAY INTERTECHNOLOGY; MFG_PN01: CRCW04020000Z0ED; ROHS: NULL; Temp Range: -55° C to +155° C
TP16 = T_POINT_R: TEST POINT PAD .035 SMT, no part to order; AGILE_PN: 510-75618; CAD_APPROVED: Yes; HEIGHT: 0.1; ROHS: Yes; SILK: 12V0_SER
TP18 = T_POINT_R: TEST POINT PAD .035 SMT, no part to order; AGILE_PN: 510-75618; CAD_APPROVED: Yes; HEIGHT: 0.1; ROHS: Yes; SILK: 1V0_SER
TP19 = T_POINT_R: TEST POINT PAD .035 SMT, no part to order; AGILE_PN: 510-75618; CAD_APPROVED: Yes; HEIGHT: 0.1; ROHS: Yes; SILK: 1V8_SER
TP20 = T_POINT_R: TEST POINT PAD .035 SMT, no part to order; AGILE_PN: 510-75618; CAD_APPROVED: Yes; HEIGHT: 0.1; ROHS: Yes; SILK: CAPVDD1_SER
TP21 = T_POINT_R: TEST POINT PAD .035 SMT, no part to order; AGILE_PN: 510-75618; CAD_APPROVED: Yes; HEIGHT: 0.1; ROHS: Yes; SILK: CAPVDD2_SER
TP24 = T_POINT_R: TEST POINT PAD .035 SMT, no part to order; AGILE_PN: 510-75618; CAD_APPROVED: Yes; HEIGHT: 0.1; ROHS: Yes; SILK: EN
U1 = MAX96789GTN: IC DUAL/SINGLE 3/6Gbps MIPI DSI to GMSL2 SERIALIZER 3.9V AEC-Q100 TQFN56; 3D_Mechanical_Footprint_File: http://fcl.am.freescale.net/ALLEGRO/step/qfn56_0p5_8x8_ep4p6.STEP; AGILE_PN: 312-83606; CAD_APPROVED: Yes; HEIGHT: 0.8; MFG_NAME01: Maxim Integrated; ROHS: Yes; Temp Range: -40 °C to +105 °C
U2 = 74AUP1G32_5P: IC GATE OR 2 INPUT 0.8-3.6V AEC-Q100 TSSOP5; 3D_Mechanical_Footprint_File: http://fcl.am.freescale.net/ALLEGRO/step/sc70-5.STEP; AGILE_PN: 312-83525; CAD_APPROVED: Yes; HEIGHT: 1.1; MFG_NAME01: Nexperia; Package Size: TSSOP-5; ROHS: Yes; Temp Range: -40  °C to +125 °C
U3 = AP7361C_5P: IC VREG LDO ADJ 0.8-5.0V 1A 2.2-6V SOT89-5; 3D_Mechanical_Footprint_File: http://fcl.am.freescale.net/ALLEGRO/step/sot-89-5.step; AGILE_PN: 315-83824; CAD_APPROVED: Yes; HEIGHT: 1.6; MFG_NAME01: DIODES INC; MFG_PN01: AP7361C-Y5-13; ROHS: Yes; Temp Range: -40 to +85C; VOLTAGE: 2.2-6V
U5 U8 U9 = 1G125: IC BUFFER/LINE DRIVER 3STATE 0.8-3.6V SC70-5; 3D_Mechanical_Footprint_File: http://fcl.am.freescale.net/ALLEGRO/step/sc70-5.STEP; AGILE_PN: 315-80956; CAD_APPROVED: Yes; HEIGHT: 1.1; MFG_NAME01: NEXPERIA; MFG_PN01: 74AUP1G125GW,125; ROHS: NULL; Temp Range: -40° C to +125° C; VOLTAGE: 0.8-3.6V
U10 = TPS22810_6P: IC LOAD SWITCH 2A 2.7-18V SOT23-6; 3D_Mechanical_Footprint_File: http://fcl.am.freescale.net/ALLEGRO/step/sot-23-6.STEP; AGILE_PN: 315-83857; CAD_APPROVED: Yes; HEIGHT: 1.45; MFG_NAME01: TEXAS INSTRUMENTS; ROHS: Yes; Temp Range: -40C to +105C; VOLTAGE: 2.7-18V
X1 X2 = XTAL_4P_B: XTAL 25MHZ 18PF 30PPM SMT; 3D_Mechanical_Footprint_File: http://fcl.am.freescale.net/ALLEGRO/step/osc4_3p2x2p5_sm.STEP; AGILE_PN: 230-78573; CAD_APPROVED: YES; Frequency Tolerance: 30ppm; HEIGHT: 0.80; MFG_NAME01: ECS Inc.; MFG_PN01: ECS-250-18-33Q-DS; Package Size: 0.126" L x 0.098" W (3.20mm x 2.50mm); ROHS: Yes; Temp Range: -40 ~ +125°C
C39 = CAP_NP: CAP CER 0.1uF 50V 10% X7R AEC-Q200 0402; AGILE_PN: 150-79461; CAD_APPROVED: Yes; FPLIST: CC0402_25,CC0402_HD,0402_CC; HEIGHT: 0.55; MFG_NAME01: MURATA; MFG_PN01: GCM155R71H104KE02D; Package Size: 0402; ROHS: NULL; Rated Voltage: 50V; Temp Range: -55C to +125C; Tolerance: 10%; VOLTAGE: 50V
R83-R86 = RES: RES MF 49.9K 1/16W 1% AEC-Q200 0402; AGILE_PN: 470-81989; CAD_APPROVED: Yes; HEIGHT: 0.4; MFG_NAME01: VISHAY INTERTECHNOLOGY; MFG_PN01: CRCW040249K9FKED; ROHS: Yes; Temp Range: -55C to +155C; Tolerance: 1%
TP1 = T_POINT_R: TEST POINT PAD .035 SMT, no part to order; AGILE_PN: 510-75618; CAD_APPROVED: Yes; HEIGHT: 0.1; ROHS: Yes; SILK: VDDD
TP2 = T_POINT_R: TEST POINT PAD .035 SMT, no part to order; AGILE_PN: 510-75618; CAD_APPROVED: Yes; HEIGHT: 0.1; ROHS: Yes; SILK: VDDA
TP22 = T_POINT_R: TEST POINT PAD .035 SMT, no part to order; AGILE_PN: 510-75618; CAD_APPROVED: Yes; HEIGHT: 0.1; ROHS: Yes; SILK: VDD18
TP23 = T_POINT_R: TEST POINT PAD .035 SMT, no part to order; AGILE_PN: 510-75618; CAD_APPROVED: Yes; HEIGHT: 0.1; ROHS: Yes; SILK: VREG
U4 = MAX96752GTN: IC DUAL/SINGLE 3/6Gbps GMSL2 to DUAL/SINGLE OLDI 1.8/3.3V TQFN56; 3D_Mechanical_Footprint_File: http://fcl.am.freescale.net/ALLEGRO/step/qfn56_0p5_8x8_ep4p6.STEP; AGILE_PN: TMP-CIP-11293; CAD_APPROVED: Yes; HEIGHT: 0.8; MFG_NAME01: MAXIM; PRE_APN: 312-83611; Package Size: 8.0 x 8.0 x 0.75 mm; ROHS: Yes; Supply Voltage: 1.8/3.3V; Temp Range: -40°C to +105°C; VOLTAGE: 1.8/3.3V
J11 J12 = CONN_HDR_3X1: HDR 1X3 TH 2.54MM SP 344H AU 118L; 3D_Mechanical_Footprint_File: http://fcl.am.freescale.net/ALLEGRO/step/hdr103_a_344h.STEP; AGILE_PN: 210-80732; ASSY_OPT: DNP; CAD_APPROVED: Yes; HEIGHT: 8.74; MFG_NAME01: WURTH ELEKTRONIK EISOS GMBH & CO. KG (ELECTRONIC & ELECTROMEHANICAL COMP); MFG_PN01: 61300311121; ROHS: Yes; Temp Range: -40°C to +105°C

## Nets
12V0SER_LOADSW_EN: R69.2 R115.1 TP24.1(TP) U10.3(EN/UVLO)
GND: BH1.1 BH2.1 BH3.1 BH4.1 BH5.1 BH6.1 BH7.1 BH8.1 C1.1 C2.1 C3.1 C4.1 C5.1 C6.1 C7.1 C8.1 C13.1 C14.2 C15.1 C16.2 C17.1 C18.2 C19.2 C20.2 C21.2 C22.2 C23.2 C24.2 C25.2 C26.2 C27.2 C28.2 C29.2 C30.2 C31.2 C32.2 C33.2 C38.1 C39.2 C40.2 C41.2 C42.1 C43.2 C44.2 C45.2 C46.1 C47.2 C48.1 C49.2 C50.1 C51.2 C52.2 C53.2 C54.2 C55.2 C80.1 C81.2 C83.2 C84.2 C86.2 J1.1(SH1) J1.2(SH2) J1.3(SH3) J1.4(SH4) J1.5(SH5) J1.6(SH6) J1.A1 J1.A4 J1.A7 J1.A12 J1.A15 J1.A18 J1.B1 J1.B4 J1.B7 J1.B12 J1.B15 J1.B18 J2.1(SH1) J2.2(SH2) J2.3(SH3) J2.4(SH4) J2.5(SH5) J2.6(SH6) J2.A1 J2.A4 J2.A7 J2.A12 J2.A15 J2.A18 J2.B1 J2.B4 J2.B7 J2.B12 J2.B15 J2.B18 J3.7(3) J3.11(SH1) J3.12(SH2) J3.13(SH3) J3.14(SH4) J4.1(A1) J4.2(B1) J4.3(A2) J4.4(B2) J5.7(3) J5.11(SH1) J5.12(SH2) J5.13(SH3) J5.14(SH4) J6.1(A1) J6.2(B1) J6.3(A2) J6.4(B2) J6.5(A3) J6.6(B3) J6.15(A8) J6.16(B8) J11.2 J12.2 Q1.2(SOURCE) Q2.2(SOURCE) Q3.2(SOURCE) Q4.2(SOURCE) Q5.2(SOURCE) Q6.2(SOURCE) Q8.2(SOURCE) R13.2 R19.2 R20.2 R21.2 R27.2 R38.2 R42.2 R43.2 R44.2 R71.2 R72.2 R83.2 R84.2 R85.2 R86.2 R89.1 R94.1 R96.1 R99.2 R101.2 R102.2 R103.2 R107.2 R109.2 R115.2 U1.57(EP) U2.3(GND) U3.2(GND) U4.57(EP) U5.2(A) U5.3(GND) U8.2(A) U8.3(GND) U9.1(~{OE}) U9.3(GND) U10.2(GND) X1.2 X1.4 X2.2 X2.4 ; also on sheet 8 9
VCC_1V0_SER: C28.1 C29.1 C30.1 C31.1 C32.1 R22.1 TP18.1(TP) U1.23(VDD) U3.5(OUT)
VCC_1V8_LVDS: C40.1 C41.1 C50.2 C51.1 C52.1 C53.1 C54.1 C55.1 J6.27(A14) J6.28(B14) J6.29(A15) J6.30(B15) J12.3 R36.1 R39.1 R40.1 R41.1 R45.1 R46.1 R104.1 R105.1 R106.1 TP22.1(TP) TP23.1(TP) U4.1(VREG) U4.2(VREGA) U4.5(VDD18_1) U4.6(VDD18_2) U4.20(VDD18_3) U4.43(VDD18_4) U4.44(VDDIO) ; also on sheet 8 9
VCC_1V8_MIPI: C1.2 C5.2 C20.1 C21.1 C22.1 C23.1 C24.1 C25.1 C26.1 C33.1 J1.B5 J1.B6 J2.B5 J2.B6 J4.27(A14) J4.28(B14) J4.29(A15) J4.30(B15) J11.3 R14.1 R16.1 R17.1 R18.1 R23.1 R24.1 R88.2 R98.1 R100.1 R108.1 TP19.1(TP) TP49.1(TP) U1.9(VDD18_1) U1.19(VDD18_2) U1.28(VDDIO) U2.5(VCC) U3.1(EN) U3.4(IN) U8.5(VCC) U9.5(VCC)
VCC_3V3_LVDS: C42.2 D3.A(ANODE) D4.A(ANODE) J12.1 R49.1 U5.5(VCC) ; also on sheet 8 9
VCC_3V3_MIPI: C2.2 C6.2 D1.A(ANODE) D2.A(ANODE) D7.A(ANODE) D14.A(ANODE) J1.B13 J1.B14 J2.B13 J2.B14 J11.1 R28.1 TP50.1(TP)
VCC_5V0_MIPI: C3.2 C7.2 J1.B16 J1.B17 J2.B16 J2.B17 TP51.1(TP)
VCC_12V0_DESCONN: C38.2 C39.1 J5.10(6) ; also on sheet 9
VCC_12V0_MIPI: C4.2 C8.2 C80.2 C81.1 C86.1 D8.A(ANODE) J1.B8 J1.B9 J2.B8 J2.B9 TP52.1(TP) U10.1(VIN)
VCC_12V0_SER: C13.2 C84.1 D12.A(ANODE) J3.10(6) R70.2 TP16.1(TP) U10.6(VOUT)
VDDA_MAX96752: C48.2 C49.1 TP2.1(TP) U4.10(VDDA)
VDDD_MAX96752: C46.2 C47.1 TP1.1(TP) U4.56(VDDD)
GMSL2_OUT0_N: C10.1 J3.4(2_2) R3.1
GMSL2_OUT0_P: C9.1 J3.3(2_1) R4.1
GMSL2_OUT1_N: C12.1 J3.1 R1.1
GMSL2_OUT1_P: C11.1 J3.2(1) R2.1
GMSL2DES_OUT0_N: C35.1 J5.4(2_2) R84.1
GMSL2DES_OUT0_P: C34.1 J5.3(2_1) R83.1
GMSL2DES_OUT1_N: C37.1 J5.1 R86.1
GMSL2DES_OUT1_P: C36.1 J5.2(1) R85.1
LDO_1V0_FB_SER: R22.2 R27.1 U3.3(ADJ)
LVDS0_BL_PWM: R114.2 ; also on sheet 8
LVDS0_CH0_CLK_N: U4.35(~{TXCLK_OUTAN}) ; also on sheet 8
LVDS0_CH0_CLK_P: U4.34(TXCLK_OUTAP) ; also on sheet 8
LVDS0_CH0_TX0_N: U4.39(~{TXOUT_A0N}) ; also on sheet 8
LVDS0_CH0_TX0_P: U4.38(TXOUT_A0P) ; also on sheet 8
LVDS0_CH0_TX1_N: U4.37(~{TXOUT_A1N}) ; also on sheet 8
LVDS0_CH0_TX1_P: U4.36(TXOUT_A1P) ; also on sheet 8
LVDS0_CH0_TX2_N: U4.33(~{TXOUT_A2N}) ; also on sheet 8
LVDS0_CH0_TX2_P: U4.32(TXOUT_A2P) ; also on sheet 8
LVDS0_CH0_TX3_N: U4.31(~{TXOUT_A3N}) ; also on sheet 8
LVDS0_CH0_TX3_P: U4.30(TXOUT_A3P) ; also on sheet 8
LVDS0_CH1_CLK_N: U4.51(~{TXCLK_OUTBN}) ; also on sheet 8
LVDS0_CH1_CLK_P: U4.50(TXCLK_OUTBP) ; also on sheet 8
LVDS0_CH1_TX0_N: U4.55(~{TXOUT_B0N}) ; also on sheet 8
LVDS0_CH1_TX0_P: U4.54(TXOUT_B0P) ; also on sheet 8
LVDS0_CH1_TX1_N: U4.53(~{TXOUT_B1N}) ; also on sheet 8
LVDS0_CH1_TX1_P: U4.52(TXOUT_B1P) ; also on sheet 8
LVDS0_CH1_TX2_N: U4.49(~{TXOUT_B2N}) ; also on sheet 8
LVDS0_CH1_TX2_P: U4.48(TXOUT_B2P) ; also on sheet 8
LVDS0_CH1_TX3_N: U4.47(~{TXOUT_B3N}) ; also on sheet 8
LVDS0_CH1_TX3_P: U4.46(TXOUT_B3P) ; also on sheet 8
LVDS0_TS_INT: R33.2 ; also on sheet 8
LVDS_EN_1: R78.2 ; also on sheet 8
LVDS_EN_2: R80.2 ; also on sheet 8
MAX96752_ERR_B: J6.25(A13) R51.1 U4.14(ERRB)
MAX96752_GPIO01_I2CSEL: J6.7(A4) R41.2 R44.1 U4.19(GPIO01/I2CSEL/VS)
MAX96752_GPIO02_MS: J6.9(A5) R39.2 R42.1 U4.45(GPIO02/WMD/MS)
MAX96752_GPIO03: R34.1 U4.40(GPIO03/MOSI/SDA1_RX1)
MAX96752_GPIO04: J6.13(A7) U4.41(GPIO04/MISO)
MAX96752_GPIO05: R35.1 U4.42(GPIO05/SCLK/SCL1_TX1)
MAX96752_GPIO06: J6.19(A10) U4.27(SDIR/GPIO6/SDA2_RX2)
MAX96752_GPIO07: J6.21(A11) U4.28(SCKIR/GPIO07)
MAX96752_GPIO08: J6.8(B4) U4.29(WSIR/GPIO08/SCL2_TX2)
MAX96752_GPIO09_CXTP: J6.10(B5) R40.2 R43.1 U4.11(CXTP/GPIO09/BNE/SS1)
MAX96752_GPIO10: J6.12(B6) R33.1 U4.12(GPIO10/RO/SS2)
MAX96752_GPIO11: J6.14(B7) R78.1 U4.24(SD/ADD0/GPO11)
MAX96752_GPIO12: J6.18(B9) R80.1 U4.25(SCK/ADD1/GPO12)
MAX96752_GPIO13: J6.20(B10) R114.1 U4.26(WS/ADD2/GPO13)
MAX96752_GPIO14: R118.1 U4.8(SDA_RX/GPIO14)
MAX96752_GPIO15: R119.1 U4.9(SCL_TX/GPIO15)
MAX96752_LOCK: J6.23(A12) R50.1 U4.13(LOCK)
MAX96752_PWDN_B: C45.1 R36.2 R37.2 U4.23(~{PWDNB})
MAX96752_SCL: R119.2 ; also on sheet 8
MAX96752_SCL1: R35.2 ; also on sheet 8
MAX96752_SDA: R118.2 ; also on sheet 8
MAX96752_SDA1: R34.2 ; also on sheet 8
MAX96752_SIOA_N: C35.2 U4.22(~{SIOAN})
MAX96752_SIOA_P: C34.2 U4.21(SIOAP)
MAX96752_SIOB_N: C37.2 U4.3(~{SIOBN})
MAX96752_SIOB_P: C36.2 U4.4(SIOBP)
MAX96752_X1: C43.1 U4.15(X1/OSC) X2.1
MAX96752_X2: C44.1 U4.16(X2) X2.3
MAX96752_XRES: R38.1 U4.18(XRES)
MAX96789_CAPVDD1: C16.1 C17.2 TP20.1(TP) U1.6(CAP_VDD_1)
MAX96789_CAPVDD2: C14.1 C15.2 TP21.1(TP) U1.22(CAP_VDD_2)
MAX96789_CFG0: J4.13(A7) R16.2 R19.1 U1.10(MFP4/CFG0/GPO4)
MAX96789_CFG1: J4.15(A8) R17.2 R20.1 U1.11(MFP5/CFG1/GPO5)
MAX96789_CFG2: J4.17(A9) R18.2 R21.1 U1.12(MFP6/CFG2/GPO6)
MAX96789_ERRB: J4.7(A4) R31.1 U1.3(MFP1/LFLTB/ERRB/GPIO01)
MAX96789_I2C-SCL: J4.26(B13) R12.1 U1.14(MFP20/SCL_TX/ODO20/GPI20)
MAX96789_I2C-SDA: J4.24(B12) R10.1 U1.13(MFP19/SDA_RX/ODO19/GPI19)
MAX96789_LMN0: R4.2 U1.31(MFP13/LMN0/GPIO13)
MAX96789_LMN1: R3.2 U1.32(MFP14/LMN1/GPIO14)
MAX96789_LMN2: R2.2 U1.53(MFP15/RO/SS2/LMN2/GPIO15)
MAX96789_LMN3: R1.2 U1.54(MFP16/BNE/SS1/LMN3/GPIO16)
MAX96789_MFP2: J4.9(A5) U1.4(MFP2/SCLK/GPIO02/GPO)
MAX96789_MFP3: J4.11(A6) U1.5(MFP3/RCLKOUT/GPIO03)
MAX96789_MFP7: J4.19(A10) R82.1 U1.24(MFP7/WS/GPIO07/GPI7)
MAX96789_MFP8: J4.21(A11) R81.1 U1.25(MFP8/SCKOR2/SCK/GPIO08/GPO8)
MAX96789_MFP9: J4.23(A12) R5.1 U1.26(MFP9/SD/GPIO09/CNTL4)
MAX96789_MFP10: J4.6(B3) R6.1 U1.27(MFP10/SDA2_RX2/WSOR/GPIO10/CNTL0)
MAX96789_MFP11: J4.8(B4) R8.1 U1.29(MFP11/SCL2_TX2/SCKOR/GPIO11/CNTL1)
MAX96789_MFP12: J4.10(B5) R7.1 U1.30(MFP12/SDOR/GPIO12/MS)
MAX96789_MFP17: J4.20(B10) R9.1 U1.55(MFP17/SDA1_RX1/MOSI/GPIO17/CNTL2)
MAX96789_MFP18: J4.22(B11) R11.1 U1.56(MFP18/SCL1_TX1/MISO/GPIO18/CNTL3)
MAX96789_MS_LOCK: J4.5(A3) R29.1 U1.2(MFP0/LOCK/MS/GPIO00)
MAX96789_PWDN_B: C27.1 R14.2 R15.2 U1.1(\\~{PWD}N)
MAX96789_SIOA_N: C10.2 U1.21(SIOAN)
MAX96789_SIOA_P: C9.2 U1.20(SIOAP)
MAX96789_SIOB_N: C12.2 U1.7(SIOBN)
MAX96789_SIOB_P: C11.2 U1.8(SIOBP)
MAX96789_XRES: R13.1 U1.18(XRES)
MIPI_DSI0_1_EN: J1.B11 R71.1 R82.2 U2.1(B)
MIPI_DSI0_BL_PWM: J1.A8 R8.2
MIPI_DSI0_CLK_N: J1.B2 U1.40(CKAN)
MIPI_DSI0_CLK_P: J1.B3 U1.39(CKAP)
MIPI_DSI0_DATA0_N: J1.A2 U1.38(DA0N)
MIPI_DSI0_DATA0_P: J1.A3 U1.37(DA0P)
MIPI_DSI0_DATA1_N: J1.A5 U1.42(DA1N)
MIPI_DSI0_DATA1_P: J1.A6 U1.41(DA1P)
MIPI_DSI0_DATA2_N: J1.A13 U1.34(DA2N)
MIPI_DSI0_DATA2_P: J1.A14 U1.33(DA2P)
MIPI_DSI0_DATA3_N: J1.A16 U1.36(DA3N)
MIPI_DSI0_DATA3_P: J1.A17 U1.35(DA3P)
MIPI_DSI0_TS_INT_B: J1.A9 R5.2
MIPI_DSI0_TS_SCL: J1.A11 R12.2
MIPI_DSI0_TS_SDA: J1.A10 R10.2
MIPI_DSI1_1_EN: J2.B11 R72.1 R81.2 U2.2(A)
MIPI_DSI1_BL_PWM: J2.A8 R6.2
MIPI_DSI1_CLK_N: J2.B2 U1.46(CKBN)
MIPI_DSI1_CLK_P: J2.B3 U1.45(CKBP)
MIPI_DSI1_DATA0_N: J2.A2 U1.44(DB0N)
MIPI_DSI1_DATA0_P: J2.A3 U1.43(DB0P)
MIPI_DSI1_DATA1_N: J2.A5 U1.48(DB1N)
MIPI_DSI1_DATA1_P: J2.A6 U1.47(DB1P)
MIPI_DSI1_DATA2_N: J2.A13 U1.50(DB2N)
MIPI_DSI1_DATA2_P: J2.A14 U1.49(DB2P)
MIPI_DSI1_DATA3_N: J2.A16 U1.52(DB3N)
MIPI_DSI1_DATA3_P: J2.A17 U1.51(DB3P)
MIPI_DSI1_TS_INT_B: J2.A9 R7.2
MIPI_DSI1_TS_SCL: J2.A11 R11.2
MIPI_DSI1_TS_SDA: J2.A10 R9.2
MIPI_DSI_EN: U2.4(Y) U8.1(~{OE}) U9.2(A)
PMIC_PG: U5.1(~{OE}) ; also on sheet 8 9
SW_CT: C83.1 U10.4(CT)
SW_QOD: R70.1 U10.5(QOD)
N20060287: C19.1 U1.15(X1/OSC) X1.1
N20060288: C18.1 U1.16(X2) X1.3
N20082822: D1.C(CATHODE) R25.2
N20082834: Q1.3(DRAIN) R25.1
N20083165: D2.C(CATHODE) R26.2
N20083177: Q2.3(DRAIN) R26.1
N20083959: Q2.1(GATE) Q3.3(DRAIN) R28.2
N20084103: Q1.1(GATE) R23.2 R29.2
N20084118: Q3.1(GATE) R24.2 R31.2
N20098940: R37.1 U5.4(Y)
N20105492: D3.C(CATHODE) R47.2
N20105494: D4.C(CATHODE) R48.2
N20105548: Q4.3(DRAIN) R47.1
N20105560: Q5.3(DRAIN) R48.1
N20105562: Q4.1(GATE) R45.2 R50.2
N20105564: Q6.1(GATE) R46.2 R51.2
N20105588: Q5.1(GATE) Q6.3(DRAIN) R49.2
N20198038: R15.1 U8.4(Y)
N20266401: J1.B10 TP25.1(TP)
N20266443: J2.B10 TP27.1(TP)
N20272842: D7.C(CATHODE) R87.2
N20272854: Q8.3(DRAIN) R87.1
N20272867: Q8.1(GATE) R88.1
N20273152: D8.C(CATHODE) R89.2
N20274335: D12.C(CATHODE) R94.2
N20275554: D14.C(CATHODE) R96.2
N20319150: J13.2(B1) R99.1
N20319151: J13.4(B2) R107.1
N20319153: J13.6(B3) R109.1
N20319312: J13.5(A3) R108.2
N20319313: J13.3(A2) R100.2
N20319314: J13.1(A1) R98.2
N20319786: J14.1(A1) R104.2
N20319788: J14.2(B1) R101.1
N20319806: J14.3(A2) R105.2
N20319808: J14.4(B2) R102.1
N20319814: J14.5(A3) R106.2
N20319816: J14.6(B3) R103.1
N20347583: R69.1 U9.4(Y)

Not connected (* = marked no-connect by the designer): J3 5(1)* 6(2)* 8(4)* 9(5)*; J4 12(B6) 14(B7) 16(B8) 18(B9) 25(A13)*; J5 5(1)* 6(2)* 8(4)* 9(5)*; J6 11(A6)* 17(A9)* 22(B11)* 24(B12)* 26(B13)*; U1 17(RSVD)*; U4 7(RSVD_1) 17(RSVD_2)

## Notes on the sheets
sheet 1
- REF DES
- JUMPER(DEFAULT)
- PAGE NAME
- Only for TEST
- J15,J16
- 1-3;2-4
- 07 LVDS_CONNECTORS
- J9
- 2-3
- 08 PMIC_LVDS_SUPPLIES
- Mount connectors and
  Connect wires between J11 and J12
  to test the SERIALISER when power is not available from MIPI (mSAS) cables
- REF DES
- ASSY_OPT
- PAGE NAME
- C83,R16,R18,R23
- DNP
- 05 MIPI_TO_GMSL_SERIALIZER
- R39,R40,R44,R45,R78,R80
- DNP
- 06 GMSL_TO_LVDS_DESERIALISE
- R53
- DNP
- 07 LVDS_CONNECTORS
- J11,J12
- DNP
- 09 Jumper Tables
sheet 2
- Revisions
- Table of Contents
- Rev
- Description
- Date
- Approved
- EB_IMX-DSI-SDSB
- X1
- DRAFT FOR REVIEW
- 5/20/22
- 01
- TITLE
- X2
- -Updated review comments
  -PMIC change to VR5500
- 5/31/22
- 02
- BLOCK_DIAGRAM
- 6/13/22
- X3
- Updated review comments from Dylan
- 03
- STACKUP
- X4
- GMSL connector changed to H-MTP
- 6/28/22
- 04
- MIPI_DSI
- REV B1
- X5
- LDO U3 changed to AP7361C
- 7/14/22
- 05
- MIPI_TO_GMSL_SERIALIZER
- Comments from Dylan.
  1. J4, J6 connectors changed to
     2x15.
  2. LVDS_EN from PGOOD of U6.
  3. 2x3 jumpers with PU-PD added.
- X6
- 7/14/22
- 06
- GMSL_TO_LVDS_DESERIALISE
- 07
- LVDS_CONNECTORS
- Comments from Johnson:
  1. Changed 12V switch U10
  2. Enable of U10 switch driven
  from DSI_EN from MIPI connector
  3. I2C connections to LVDS1 made
      separate
- 08
- PMIC_LVDS_SUPPLIES
- (DSI SERDES BOARD)
- X7
- 8/3/22
- 09
- Jumper Tables
- 1. 12V and GND connection on HMTD
  connector chnaged for easy route.
  2. Release design for mfg
- A
- 8/12/22
- 1. MAX96789 SDA_RX&SCL_TX is
  connected to MIPI_DSI0 port and
  SDA1_RX1&SCL1_TX1 is connected
  to MIPI_DSI1 port.
  2. MAX96752 SDA_RX&SCL_TX(PIN8&9)
  to both LVDS0 and LVDS1 miniSAS
  connectors.
- AX1
- 7/24/23
- Comments from Johnson -
  Move MAX96752_I2C1 and
  MAX96752_I2C connections to both
   LVDS connectors through jumper
  selection.
- AX2
- 7/25/23
- B
- Release for MFG
- 8/1/23
- B1
- Defined R71 and R72 as DNP.
- 26/7/24
sheet 3
- BLOCK DIAGRAM
sheet 5
- MIPI DSI
  (MINI SAS CONNECTORS)
- I2C pullup on host brd
- I2C pullup on host brd
- Place TP near connector
- Mini-SAS cables cross connect the  Ax pins to Bx (x=1 to 18)
- MOUNTING HOLES
  (Place on corners of VCUT boards)
- LED for POWER
sheet 6
- GMSL2+ SERIALISER
- H-MTD CONNECTOR
- CONNECTOR 12V SWITCH
- Cin=10*Cout
- Discharge time:
  Without cable : 0.94msec
  With Cable      : 76msec
- HEADER FOR ALL SER PINS
- CFG JUMPERS
- PU-> Pull-up resistor; PD -> Pull down resistor
  CFG0 :
    PU- OPEN;  PD- GND : I2C MODE/ ADD 0x80
  CFG1 :
    PU- 4.42K;  PD- 5.62K : STP MODE / GMSL2 (3Gbps)
  CFG2 :
    PU- OPEN;  PD- GND : HIBW/BWS 24 BIT / RCLKOUT DISABLED
- "OR"
- LED's LOCK AND ERRB
- 1V LDO
- 1V@345mA
- MS
    LOW  : BASE MODE
    HIGH : BYPASS MODE
- VOUT= 0.8*(1+14K/56K)= 1V
sheet 7
- GMSL2+ DESERIALISER
- H-MTD CONNECTOR
- PLACE 10nF NEAR VDD18 AND VDDIO PINS
- JUMPER FOR ALL PINS
- LED's FOR LOCK AND ERRB
- CONFIGURATION OPTIONS
- MS
    LOW  : BASE MODE
    HIGH : BYPASS MODE
- CXTP
    LOW  : TWISTED PAIR MODE
    HIGH : COAX MODE
- I2CSEL
    LOW  : UART ENABLED
    HIGH : I2C ENABLED
